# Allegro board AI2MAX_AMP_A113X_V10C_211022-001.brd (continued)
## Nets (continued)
GND: C1.2 C2.2 C3.2 C4.2 C6.2 C7.2 C9.1 C12.1 C13.2 C14.1 C16.2 C17.1 C18.2 C20.1 C21.2 C22.2 C25.1 C30.2 C51.2 C52.1 C54.2 C55.1 C56.2 C57.2 C58.1 C60.2 C61.1 C62.2 C65.1 C66.1 C67.1 C68.2 C69.1 C71.2 C72.1 C73.2 C75.1 C76.2 C77.2 C78.2 C79.2 C101.1 C102.1 C103.1 C104.1 C105.1 C106.1 C201.2 C203.1 C204.1 C205.2 C206.2 C207.1 C208.1 C209.2 C211.2 C214.2 C216.1 C217.1 C218.2 C219.1 C221.1 C222.1 C223.2 C224.2 C226.1 C228.1 C229.1 C230.2 C231.2 C232.1 C233.2 C235.2 C238.2 C240.1 C241.1 C242.2 C243.1 C245.1 C246.1 C248.2 C249.2 C250.1 C251.1 C252.1 C253.1 C254.1 C255.2 C256.2 C257.2 C258.2 C259.1 C260.2 C261.1 C262.2 C264.2 C265.1 C268.2 C269.1 C301.2 C303.1 C304.1 C305.2 C306.2 C307.1 C308.1 C309.2 C311.2 C314.2 C316.1 C317.1 C318.2 C319.1 C321.1 C322.1 C323.2 C324.2 C326.1 C328.1 C329.1 C330.2 C331.2 C332.1 C333.2 C335.2 C338.2 C340.1 C341.1 C342.2 C343.1 C345.1 C346.1 C348.2 C349.1 C350.1 C351.1 C352.1 C353.2 C354.2 C355.2 C356.2 C357.1 C358.2 C359.1 C360.2 C362.2 C363.1 C366.2 C367.1 J813.3 J813.9 J813.13 J813.15 J813.S1 J813.S2 J813.S3 J813.S4 J813.S5 J814.5(GND#5) J814.6(S1) J814.7(S2) J814.8(S3) J814.9(S4) J814.10(GND#10) J814.11(GND#11) Q2.2(EMITTER) Q3.2(EMITTER) Q4.2(EMITTER) Q5.2(EMITTER) R3.1 R7.1 R9.1 R11.1 R21.1 R22.1 R59.1 R60.1 R63.1 R201.2 R204.1 R205.2 R207.1 R220.1 R221.2 R223.1 R233.1 R234.2 R235.1 R236.2 R301.2 R304.1 R305.2 R319.1 R321.2 R339.1 R340.2 R341.1 R342.2 T1.2 T308.1(TP) T311.1(TP) T312.1(TP) T313.1(TP) T314.1(TP) T315.1(TP) T318.1(TP) T320.1(TP) T321.1(TP) U1.A9(DVSS#A9) U1.A14(DVSS#A14) U1.B4(DVSS#B4) U1.B17(DVSS#B17) U1.D5(DVSS#D5) U1.D7(DVSS#D7) U1.D9(DVSS#D9) U1.D12(DVSS#D12) U1.D14(DVSS#D14) U1.E4(DVSS#E4) U1.E5(DVSS#E5) U1.E6(DVSS#E6) U1.E7(DVSS#E7) U1.E8(DVSS#E8) U1.E9(DVSS#E9) U1.E10(DVSS#E10) U1.E11(DVSS#E11) U1.E12(DVSS#E12) U1.E13(DVSS#E13) U1.F3(DVSS#F3) U1.F4(DVSS#F4) U1.F7(DVSS#F7) U1.F8(DVSS#F8) U1.F9(DVSS#F9) U1.F10(DVSS#F10) U1.F11(DVSS#F11) U1.F14(DVSS#F14) U1.G7(DVSS#G7) U1.G8(DVSS#G8) U1.G9(DVSS#G9) U1.G10(DVSS#G10) U1.G11(DVSS#G11) U1.G12(DVSS#G12) U1.G13(DVSS#G13) U1.H1(DVSS#H1) U1.H6(DVSS#H6) U1.H7(DVSS#H7) U1.H8(DVSS#H8) U1.H9(DVSS#H9) U1.H10(DVSS#H10) U1.H11(DVSS#H11) U1.H14(DVSS#H14) U1.H15(DVSS#H15) U1.J7(DVSS#J7) U1.J8(DVSS#J8) U1.J9(DVSS#J9) U1.J10(DVSS#J10) U1.J11(DVSS#J11) U1.J14(DVSS#J14) U1.J17(DVSS#J17) U1.K2(DVSS#K2) U1.K4(DVSS#K4) U1.K5(DVSS#K5) U1.K6(DVSS#K6) U1.K7(DVSS#K7) U1.K8(DVSS#K8) U1.K9(DVSS#K9) U1.K10(DVSS#K10) U1.K12(DVSS#K12) U1.K13(DVSS#K13) U1.L4(DVSS#L4) U1.L5(DVSS#L5) U1.L6(DVSS#L6) U1.L7(DVSS#L7) U1.L8(DVSS#L8) U1.L9(DVSS#L9) U1.L11(DVSS#L11) U1.L12(DVSS#L12) U1.L13(DVSS#L13) U1.L14(DVSS#L14) U1.L15(DVSS#L15) U1.M4(DVSS#M4) U1.M5(DVSS#M5) U1.M9(DVSS#M9) U1.M12(DVSS#M12) U1.M13(DVSS#M13) U1.M14(DVSS#M14) U1.M17(DVSS#M17) U1.N2(DVSS#N2) U1.N3(DVSS#N3) U1.N6(DVSS#N6) U1.N7(DVSS#N7) U1.N9(DVSS#N9) U1.N10(DVSS#N10) U1.N15(DVSS#N15) U1.P2(DVSS#P2) U1.P3(DVSS#P3) U1.P4(DVSS#P4) U1.P5(DVSS#P5) U1.P8(DVSS#P8) U1.P11(DVSS#P11) U1.P14(DVSS#P14) U1.R3(DVSS#R3) U1.R8(DVSS#R8) U1.R17(DVSS#R17) U1.T1(DVSS#T1) U1.T5(DVSS#T5) U1.T9(DVSS#T9) U1.T12(DVSS#T12) U1.T15(DVSS#T15) U1.U3(DVSS#U3) U1.U6(DVSS#U6) U1.U10(DVSS#U10) U1.U13(DVSS#U13) U1.U16(DVSS#U16) U2.4(GND) U2.9(E-PAD) U3.2(GND) U51.2(GND) U52.2(GND) U53.2(GND) U54.2(GND) U55.2(GND) U201.1(NC1) U201.3(NC2) U201.4(GND) U201.5(NC3) U201.9(NC4) U201.17(PGND2B) U201.22(PGND2A) U201.25(AGND) U201.26(NC5) U201.29(PGND1B) U201.34(PGND1A) U201.39(GND_IO) U201.41(E_PAD) U202.1(NC1) U202.3(NC2) U202.4(GND) U202.5(NC3) U202.9(NC4) U202.17(PGND2B) U202.22(PGND2A) U202.25(AGND) U202.26(NC5) U202.29(PGND1B) U202.34(PGND1A) U202.39(GND_IO) U202.41(E_PAD) U301.1(NC1) U301.3(NC2) U301.4(GND) U301.5(NC3) U301.9(NC4) U301.17(PGND2B) U301.22(PGND2A) U301.25(AGND) U301.26(NC5) U301.29(PGND1B) U301.34(PGND1A) U301.39(GND_IO) U301.41(E_PAD) U302.1(NC1) U302.3(NC2) U302.4(GND) U302.5(NC3) U302.9(NC4) U302.17(PGND2B) U302.22(PGND2A) U302.25(AGND) U302.26(NC5) U302.29(PGND1B) U302.34(PGND1A) U302.39(GND_IO) U302.41(E_PAD) UNK2C1.1 UNK2C2.1 UNK2C3.1 UNK2C4.2 UNK2C5.1 UNK2C6.2 UNK2C7.1 UNK2C8.1 UNK2C9.1 UNK2C10.1 UNK2C11.1 UNK2C12.1 UNK2C13.2 UNK2C14.1 UNK2C15.1 UNK2C16.1 UNK2C17.2 UNK2C19.1 UNK2C20.1 UNK2C22.1 UNK2CON1.1 UNK2D3.2 UNK2D4.2 UNK2Q1.2 UNK2R14.2 UNK2R15.1 UNK2T17.1 UNK2T25.1 UNK2T28.1 UNK2U2.1 UNK2Y2.2 UNK2Y2.4 UNK3C1.1 UNK3C2.1 UNK3C4.1 UNK3C5.1 UNK3C6.2 UNK3C8.2 UNK3C9.1 UNK3C10.1 UNK3C11.1 UNK3C12.1 UNK3C18.1 UNK3C19.1 UNK3C20.1 UNK3C21.1 UNK3C26.2 UNK3C27.1 UNK3C28.2 UNK3C30.1 UNK3C31.1 UNK3C35.1 UNK3C38.1 UNK3C39.1 UNK3C40.1 UNK3C42.1 UNK3C45.1 UNK3C46.1 UNK3C58.1 UNK3C62.1 UNK3R6.1 UNK3R10.1 UNK3R20.1 UNK3U1.A9 UNK3U1.B1 UNK3U1.B3 UNK3U1.B9 UNK3U1.D1 UNK3U1.D8 UNK3U1.E1 UNK3U1.E2 UNK3U1.E8 UNK3U1.F9 UNK3U1.G1 UNK3U1.G8 UNK3U1.G9 UNK3U1.J2 UNK3U1.J8 UNK3U1.M1 UNK3U1.M9 UNK3U1.P1 UNK3U1.P9 UNK3U1.T1 UNK3U1.T9 UNK4C2.1 UNK4C3.1 UNK4C4.1 UNK4C5.2 UNK4C8.1 UNK4C9.1 UNK4C10.1 UNK4C11.1 UNK4C17.1 UNK4C18.1 UNK4C26.1 UNK4C34.1 UNK4C35.1 UNK4C47.2 UNK4C48.1 UNK4C49.1 UNK4K2.1 UNK4K2.2 UNK4R2.1 UNK4R7.1 UNK4R9.2 UNK4R13.1 UNK4R52.1 UNK4U5.2 UNK4U5.13 UNK4U5.23 UNK4U5.25 UNK4U5.27 UNK4U5.33 UNK4U5.36 UNK4U5.40 UNK4U5.46 UNK4U5.48 UNK4U9.AA4 UNK4U9.AA6 UNK4U9.H6 UNK4U9.K4 UNK4U9.M7 UNK4U9.P5 UNK4U9.R10 UNK4U9.T5 UNK4U9.U8 UNK4U9.Y2 UNK4U9.Y5 UNK5C3.1 UNK5C9.1 UNK5C10.1 UNK5C11.1 UNK5C13.1 UNK5D11.2 UNK5D12.2 UNK5R64.2 UNK5R78.2
VCC5V: C6.1 C7.1 C9.2 C10.2 C13.1 C14.2 C51.1 C52.2 C57.1 C58.2 C68.1 C69.2 J814.1(VBUS) L1.2 R6.2 R10.2 R17.1 R18.1 R52.2 R329.1 R330.1 R334.1 R337.2 U3.5(IN) U51.5(IN) U52.5(IN) U53.5(IN) UNK5C13.2 UNK5R5.1
VCC_3.3V: C22.1 C79.1 Q1.3(D) U1.A5(VDDIO_Z) U1.K15(AVDD33_USB) U55.1(VIN) U55.3(ON/OFF) UNK2C22.2 UNK2R18.1 UNK2R19.1 UNK2T15.1 UNK4C4.2 UNK4C5.1 UNK4C8.2 UNK4C17.2 UNK4C18.2 UNK4C49.2 UNK4R6.2 UNK4U5.1 UNK4U5.12 UNK4U5.24 UNK4U5.37 UNK4U9.M6 UNK4U9.N5 UNK4U9.T10 UNK4U9.U9 UNK5C10.2
VDD_EE: C60.1 C61.2 C62.1 C64.2 L52.2 R15.2 R53.2 R333.2 U1.F12(VDD_EE#F12) U1.J3(VDD_EE#J3) U1.J4(VDD_EE#J4) U1.J5(VDD_EE#J5) U1.J6(VDD_EE#J6) U1.K11(VDD_EE#K11) UNK1R2.2 UNK2C1.2 UNK2C11.2 UNK2C13.1 UNK2C16.2 UNK2C20.2 UNK2R27.2
VDDAO_3.3V: C16.1 C17.2 C18.1 C19.2 C21.1 C23.2 C101.2 C201.1 C230.1 C249.1 C250.2 C301.1 C330.1 L2.2 Q1.2(S) R8.2 R12.2 R62.1 R105.1 R214.2 R307.1 R314.2 R323.1 R335.1 R336.1 R348.1 R349.1 R350.1 R351.1 T129.1(TP) T316.1(TP) T319.1(TP) U1.D13(VDDIO_AO) U1.K14(VDDIO_A) U201.40(VDD_IO) U202.40(VDD_IO) U301.40(VDD_IO) U302.40(VDD_IO) UNK2C5.2 UNK2C15.2 UNK2CON1.3 UNK2D7.1 UNK2R2.1 UNK2R24.1 UNK2R28.1 UNK2U2.3
VDDCPU: C54.1 C55.2 C56.1 C63.2 L51.2 R51.2 U1.F5(VDDCPU#F5) U1.F6(VDDCPU#F6) U1.G3(VDDCPU#G3) U1.G4(VDDCPU#G4) U1.G5(VDDCPU#G5) U1.G6(VDDCPU#G6) U1.H3(VDDCPU#H3) U1.H4(VDDCPU#H4) U1.H5(VDDCPU#H5) UNK1R1.2 UNK2C2.2 UNK2C4.1 UNK2C6.1 UNK2C7.2 UNK2C8.2 UNK2C14.2 UNK2C19.2
VDDCPU_EN: R54.1 U1.C4(TESTN) UNK2R2.2
VDDCPU_PWM: R56.2 U1.D3(GPIOAO_2//UART_CTS_AO_B//UART_C) UNK1R1.1
VDDEE_PWM: R58.2 U1.D4(GPIOAO_9//I2C_SDA_AO//PWMAO_D) UNK1R2.1
VDDIO_AO18: C76.1 R106.1 U1.H12(AVDD18_SAR_PLL) U1.H13(VDD18_XTAL_IOVREF) U1.J12(AVDD18_DDRPLL) U1.J13(AVDD18_USB) U54.5(VOUT) UNK2C10.2 UNK2C12.2 UNK2C17.1 UNK2R3.2 UNK2R29.2 UNK3C1.2 UNK5C9.2 UNK5R20.1
VDDIO_BOOT: U1.L3(VDDIO_BOOT) UNK4C2.2 UNK4C10.2 UNK4C11.2 UNK4C34.2 UNK4C35.2 UNK4C47.1 UNK4C48.2 UNK4R1.2 UNK4R3.1 UNK4R4.1 UNK4R5.1 UNK4R6.1 UNK4R8.1 UNK4R12.2 UNK4R14.1 UNK4R16.1 UNK4U5.28 UNK4U5.34 UNK4U5.45 UNK4U9.AA3 UNK4U9.AA5 UNK4U9.K6 UNK4U9.W4 UNK4U9.Y4
VDDIO_X: C102.2 R105.2 R106.2 U1.C8(VDDIO_X)
VDDQ1.35V: C71.1 C72.2 C73.1 C74.2 L53.2 R61.2 U1.M6(VDDQ#M6) U1.M7(VDDQ#M7) U1.M8(VDDQ#M8) U1.M10(VDDQ#M10) U1.M11(VDDQ#M11) U1.N4(VDDQ#N4) U1.N5(VDDQ#N5) UNK3C2.2 UNK3C4.2 UNK3C5.2 UNK3C6.1 UNK3C8.1 UNK3C9.2 UNK3C10.2 UNK3C11.2 UNK3C12.2 UNK3C18.2 UNK3C19.2 UNK3C20.2 UNK3C21.2 UNK3C26.1 UNK3C28.1 UNK3C30.2 UNK3C31.2 UNK3C35.2 UNK3C38.2 UNK3C39.2 UNK3C42.2 UNK3C45.2 UNK3C58.2 UNK3C62.2 UNK3R8.2 UNK3R19.2 UNK3U1.A1 UNK3U1.A8 UNK3U1.B2 UNK3U1.C1 UNK3U1.C9 UNK3U1.D2 UNK3U1.D9 UNK3U1.E9 UNK3U1.F1 UNK3U1.G7 UNK3U1.H2 UNK3U1.H9 UNK3U1.K2 UNK3U1.K8 UNK3U1.N1 UNK3U1.N9 UNK3U1.R1 UNK3U1.R9
ACTIVE_STBY: R219.1 R320.1 U1.B11(GPIOX_19//I2C_SDA_C//UART_CTS_E)
AMP_RESET: R215.1 R315.1 T317.1(TP) UNK5R74.2
AMP_SCL: R209.1 U1.A16(GPIOAO_10//I2C_SLAVE_SCK_AO//I2) UNK2R24.2 UNK5R66.2
AMP_SCL_DEV: R209.2 R238.1 R309.1 T306.1(TP)
AMP_SDA: R210.1 U1.B15(GPIOAO_11//I2C_SLAVE_SDA_AO//I2) UNK2R28.2 UNK5R65.2
AMP_SDA_DEV: R210.2 R239.1 R310.1 T305.1(TP)
BCLK: J813.11 UNK5R68.1
CPU_RESET: R240.1 R338.1 U1.A12(RESETN) UNK2R14.1 UNK2U2.2
CTRL_A113X: UNK5R75.2 UNK5R76.1 UNK5R77.1
DATA: J813.12 UNK5R69.1
DDR3_A0: U1.R12(A0) UNK3U1.N3
DDR3_A1: U1.U15(A1) UNK3U1.P7
DDR3_A2: U1.P16(A2) UNK3U1.P3
DDR3_A3: U1.U17(A3) UNK3U1.N2
DDR3_A4: U1.R11(A4) UNK3U1.P8
DDR3_A5: U1.T14(A5) UNK3U1.P2
DDR3_A6: U1.P12(A6) UNK3U1.R8
DDR3_A7: U1.U14(A7) UNK3U1.R2
DDR3_A8: U1.P13(A8) UNK3U1.T8
DDR3_A9: U1.T16(A9) UNK3U1.R3
DDR3_A10: U1.R10(A10) UNK3U1.L7
DDR3_A11: U1.P17(A11) UNK3U1.R7
DDR3_A12: U1.T17(A12) UNK3U1.N7
DDR3_A13: U1.R15(A13) UNK3U1.T3
DDR3_A14: U1.R14(A14(A14/WE_N)) UNK3U1.T7
DDR3_A15: U1.T13(A15(A15/CAS_N)) UNK3U1.M7
DDR3_BA0: U1.N16(BA_0) UNK3U1.M2
DDR3_BA1: U1.U12(BA_1) UNK3U1.N8
DDR3_BA2: U1.M16(BA_2(BG0)) UNK3U1.M3
DDR3_CAS: U1.P15(CAS_N(ACT_N)) UNK3U1.K3
DDR3_CKE0: U1.P10(CKE0) UNK3U1.K9
DDR3_CLKN: U1.T10(CKN) UNK3C7.1 UNK3R2.2 UNK3U1.K7
DDR3_CLKP: U1.U9(CKP) UNK3C7.2 UNK3R2.1 UNK3U1.J7
DDR3_DQ0: U1.T2(DQ0) UNK3U1.A2
DDR3_DQ1: U1.T3(DQ1) UNK3U1.C2
DDR3_DQ2: U1.P6(DQ2) UNK3U1.A7
DDR3_DQ3: U1.U7(DQ3) UNK3U1.D7
DDR3_DQ4: U1.U1(DQ4) UNK3U1.A3
DDR3_DQ5: U1.U2(DQ5) UNK3U1.C3
DDR3_DQ6: U1.R6(DQ6) UNK3U1.B8
DDR3_DQ7: U1.T7(DQ7) UNK3U1.C8
DDR3_DQ8: U1.T8(DQ8) UNK3U1.H7
DDR3_DQ9: U1.R2(DQ9) UNK3U1.F2
DDR3_DQ10: U1.R9(DQ10) UNK3U1.H8
DDR3_DQ11: U1.R4(DQ11) UNK3U1.E3
DDR3_DQ12: U1.R7(DQ12) UNK3U1.F8
DDR3_DQ13: U1.P1(DQ13) UNK3U1.H3
DDR3_DQ14: U1.P9(DQ14) UNK3U1.F7
DDR3_DQ15: U1.R1(DQ15) UNK3U1.G2
DDR3_DQM0: U1.R5(DQM0) UNK3U1.D3
DDR3_DQM1: U1.P7(DQM1) UNK3U1.E7
DDR3_DQSN0: U1.T6(DQSN_0) UNK3U1.B7
DDR3_DQSN1: U1.T4(DQSN_1) UNK3U1.G3
DDR3_DQSP0: U1.U5(DQSP_0) UNK3U1.C7
DDR3_DQSP1: U1.U4(DQSP_1) UNK3U1.F3
DDR3_NCS0: U1.U11(CS0_N) UNK3U1.L2
DDR3_ODT0: U1.R16(ODT0) UNK3U1.K1
DDR3_RAS: U1.T11(RAS_N(A16/RAS_N)) UNK3U1.J3
DDR3_RST: U1.M15(RST_N) UNK3C46.2 UNK3R8.1 UNK3U1.T2
DDR3_WE: U1.R13(WE_N(BG1)) UNK3U1.L3
EMMC_1.8V: C77.1 U55.5(VOUT) UNK4R5.2
GPIOX_16: T125.1(TP) U1.D10(GPIOX_16//I2C_SCK_B//UART_TX_EE)
GPIOX_17: T126.1(TP) U1.D8(GPIOX_17//I2C_SDA_B//UART_RX_EE)
GPIOX_18: T127.1(TP) U1.C10(GPIOX_18//I2C_SCK_C//UART_RTS_E)
GPIOZ_10: U1.E2(GPIOZ_10) UNK2T3.1
HW_VS: U1.D15(SARADC_CH1) UNK2R3.1 UNK2R15.2
I2SIN_BCLK_C: C103.2 R107.2 R227.1 R229.1 R325.1 R327.1 R343.2 T309.1(TP) UNK5R68.2
I2SIN_DATA_C: R103.2 R104.2 UNK5R69.2
I2SIN_LRCK_C: C104.2 R108.2 R228.1 R230.1 R326.1 R328.1 R344.2 T307.1(TP) UNK5R67.2
I2SIN_MCLK_B: R102.2 UNK5R70.2
I2SO_DATA0: C105.2 R109.2 R225.2 R231.2 U201.7(SDATA) U301.7(SDATA)
I2SO_DATA1: C106.2 R110.2 R226.2 R231.1 U202.7(SDATA) U302.7(SDATA)
I2SO_MCLK_A: R101.2 T101.1(TP)
IR_IN: U1.B14(GPIOAO_6//IR_REMOTE_INPUT) UNK2T6.1
IR_OUT: U1.B13(GPIOAO_7//IR_REMOTE_OUT//JTAG_T) UNK2T5.1
LCD_BL_EN: U1.B1(GPIOZ_5//SPI_SS2_A//PWM_A//SPDI) UNK2T21.1
LCD_BL_PWM: U1.C7(GPIOZ_4//SPI_SS1_A//PWM_B//SPDI) UNK2T22.1
LCD_RESET: U1.C2(GPIOZ_6//I2C_SCK_A//UART_CTS_AO) UNK2T24.1
LINE_OUT_DET: U1.D2(GPIOZ_7//I2C_SDA_A//UART_RTS_AO) UNK2T23.1
LINUX_RX: U1.B12(GPIOAO_1//UART_RX_AO_A) UNK2D4.1 UNK2R1.2
LINUX_TX: U1.A13(GPIOAO_0//UART_TX_AO_A) UNK2D3.1 UNK2R16.2
LRCK: J813.10 UNK5R67.1
MCLK: J813.14 UNK5R70.1
MDDR3_VREF1: UNK3C27.2 UNK3C40.2 UNK3R19.1 UNK3R20.2 UNK3U1.H1 UNK3U1.M8
NAND_ALE: U1.M1(BOOT_9//EMMC_RST//NAND_ALE//NOR) UNK4U5.17 UNK4U9.U5
NAND_CLE: U1.L2(BOOT_10//EMMC_CMD//NAND_CLE) UNK4R14.2 UNK4U5.16 UNK4U9.W5
NAND_CS1: U1.L1(BOOT_8//EMMC_CLK//NAND_CE0) UNK4C3.2 UNK4R1.1 UNK4R11.1 UNK4R11.2 UNK4U5.9 UNK4U9.W6
NAND_D0: U1.F2(BOOT_0//EMMC_D0) UNK4R16.2 UNK4R19.1 UNK4R19.2 UNK4U5.29 UNK4U9.H3
NAND_D1: U1.F1(BOOT_1//EMMC_D1) UNK4R20.1 UNK4R20.2 UNK4U5.30 UNK4U9.H4
NAND_D2: U1.G1(BOOT_2//EMMC_D2) UNK4R21.1 UNK4R21.2 UNK4U5.31 UNK4U9.H5
NAND_D3: U1.G2(BOOT_3//EMMC_D3//NOR_HOLDN) UNK4R22.1 UNK4R22.2 UNK4U5.32 UNK4U9.J2
NAND_D4: U1.H2(BOOT_4//EMMC_D4//NOR_D//POC0) UNK4R23.1 UNK4R23.2 UNK4R52.2 UNK4U5.41 UNK4U9.J3
NAND_D5: U1.J1(BOOT_5//EMMC_D5//NOR_Q//POC1) UNK4R10.2 UNK4R24.1 UNK4R24.2 UNK4U5.42 UNK4U9.J4
NAND_D6: U1.J2(BOOT_6//EMMC_D6//NOR_C//POC2) UNK4R13.2 UNK4R25.1 UNK4R25.2 UNK4U5.43 UNK4U9.J5
NAND_D7: U1.K1(BOOT_7//EMMC_D7//POC3) UNK4R2.2 UNK4R26.1 UNK4R26.2 UNK4U5.44 UNK4U9.J6
NAND_NR/B: U1.K3(BOOT_13//EMMC_DS//NAND_RB) UNK4R9.1 UNK4R12.1 UNK4R17.1 UNK4U5.6 UNK4U5.7
NAND_NRE: U1.M2(BOOT_12//NAND_REN_WR) UNK4R18.1 UNK4R18.2 UNK4U5.8
NAND_NWE: U1.N1(BOOT_11//NAND_WEN_CLK) UNK4R15.1 UNK4R15.2 UNK4U5.18
NAND_PSL: UNK4R3.2 UNK4U5.39
NAND_VSP: UNK4R7.2 UNK4R8.2 UNK4U5.38
NPWM_OFF1: R219.2 U201.12(\\F\A\U\L\T) U202.12(\\F\A\U\L\T)
NPWM_OFF2: R320.2 U301.12(\\F\A\U\L\T) U302.12(\\F\A\U\L\T)
NRESET_AMP: R216.1 R316.1 U1.B6(GPIOX_20//PWM_A)
NRST_AMP1: C204.2 C226.2 R215.2 R216.2 R240.2 U201.36(\\R\E\S\E\T) U202.36(\\R\E\S\E\T)
NRST_AMP2: C304.2 C326.2 R315.2 R316.2 R338.2 U301.36(\\R\E\S\E\T) U302.36(\\R\E\S\E\T)
OUT1A_B_LF: C233.1 C237.1 C261.2 C267.1 FB203.1 L203.2 L213.2 R220.2
OUT1A_B_LW: C209.1 C213.1 C259.2 C263.1 FB202.2 L201.2 L211.2 R204.2
OUT1A_B_RF: C333.1 C337.1 C359.2 C365.1 FB303.1 L303.2 L313.2 R319.2
OUT1A_B_RW: C309.1 C313.1 C357.2 C361.1 FB302.2 L301.2 L311.2 R304.2
OUT2A_B_LF: C237.2 C240.2 C262.1 C270.2 FB204.1 L204.2 L214.2 R221.1
OUT2A_B_LW: C213.2 C216.2 C260.1 C266.2 FB201.2 L202.2 L212.2 R205.1
OUT2A_B_RF: C337.2 C340.2 C360.1 C368.2 FB304.1 L304.2 L314.2 R321.1
OUT2A_B_RW: C313.2 C316.2 C358.1 C364.2 FB301.2 L302.2 L312.2 R305.1
PDM_DCLK: T102.1(TP) U1.E16(GPIOA_14//PDM_DCLK//CLKSYN_IN//)
PDM_DIN0: T103.1(TP) U1.E17(GPIOA_15//PDM_DIN0//PWM_B)
PDM_DIN1: T104.1(TP) U1.D16(GPIOA_16//PDM_DIN1//PWM_C)
PDM_DIN2: T105.1(TP) U1.D17(GPIOA_17//PDM_DIN2//I2C_SDA_C//)
PDM_DIN3: T106.1(TP) U1.C17(GPIOA_18//PDM_DIN3//I2C_SCK_C//)
POWERSTB: R12.1 R13.1 U1.C12(GPIOAO_12//CLK12_24//PWMAO_B)
PVREF: U1.N11(PVREF) UNK3T1.1
PWR_24V: C1.1 C2.1 C3.1 C4.1 C30.1 C205.1 C206.1 C223.1 C224.1 C231.1 C248.1 C255.1 C256.1 C257.1 C258.1 C305.1 C306.1 C323.1 C324.1 C331.1 C348.1 C353.1 C354.1 C355.1 C356.1 R1.2 T1.1 U2.2(VIN) U201.19(PVDD2B) U201.20(PVDD2A) U201.31(PVDD1B) U201.32(PVDD1A) U202.19(PVDD2B) U202.20(PVDD2A) U202.31(PVDD1B) U202.32(PVDD1A) U301.19(PVDD2B) U301.20(PVDD2A) U301.31(PVDD1B) U301.32(PVDD1A) U302.19(PVDD2B) U302.20(PVDD2A) U302.31(PVDD1B) U302.32(PVDD1A)
RMII_MDC: T322.1(TP) U1.A11(GPIOX_22//ETH_MDC)
RMII_MDIO: T323.1(TP) U1.A8(GPIOX_21//ETH_MDIO)
RMII_RXCLK: T325.1(TP) U1.B7(GPIOX_12//TDMA_SCLK//TDMA_SLV_S)
RMII_RXD0: T327.1(TP) U1.B8(GPIOX_13//TDMA_FS//TDMA_SLV_FS/)
RMII_RXD1: T326.1(TP) U1.A6(GPIOX_14//TDMA_DIN0//TDMA_DOUT0)
RMII_RXDV: T324.1(TP) U1.A7(GPIOX_15//TDMA_DOUT0//TDMA_DOUT)
RMII_TXD0: T328.1(TP) U1.A10(GPIOX_8//UART_TX_EE_A//RMII_TXD)
RMII_TXD1: T331.1(TP) U1.C9(GPIOX_9//UART_RX_EE_A//RMII_TXD)
RMII_TXEN: T329.1(TP) U1.B9(GPIOX_10//UART_CTS_EE_A//PWM_C/)
SCL: J813.8 UNK5R66.1
SCL_AMP1: C222.2 C246.2 R211.2 R238.2 R349.2 U201.11(SCL) U202.11(SCL)
SCL_AMP2: C322.2 C346.2 R309.2 R311.2 R351.2 U301.11(SCL) U302.11(SCL)
SDA: J813.7 UNK5R65.1
SDA_AMP1: C217.2 C241.2 R212.2 R239.2 R348.2 U201.10(SDA) U202.10(SDA)
SDA_AMP2: C317.2 C341.2 R310.2 R312.2 R350.2 U301.10(SDA) U302.10(SDA)
SPDIF_IN: T107.1(TP) U1.E14(GPIOA_19//SPDIF_IN//SPDIF_OUT//)
SPDIF_OUT: T108.1(TP) U1.C16(GPIOA_20//SPDIF_OUT//SPDIF_IN//)
SPI_CLK: U1.C6(GPIOZ_0//SPI_CLK_A//UART_RTS_EE) UNK2T16.1
SPI_MISO: U1.D6(GPIOZ_2//SPI_MISO_A//UART_TX_EE) UNK2T19.1
SPI_MOSI: U1.C5(GPIOZ_1//SPI_MOSI_A//UART_CTS_E) UNK2T18.1
SPI_SS0: U1.C1(GPIOZ_3//SPI_SS0_A//UART_RX_EE_) UNK2T20.1
SPK_I2C_SCK: R211.1 R311.1 U1.E3(GPIOZ_8//I2C_SCK_B//UART_TX_AO_) UNK2R18.2 UNK2T26.1
SPK_I2C_SDA: R212.1 R312.1 U1.D1(GPIOZ_9//I2C_SDA_B//UART_RX_AO_) UNK2R19.2 UNK2T27.1
SPK_RST: U1.C15(GPIOAO_4//UART_TX_AO_B//I2C_SCK) UNK2T8.1
STANDBY_A113X: U1.C13(GPIOAO_8//CLK_32K_IN//I2C_SCK_A) UNK5R77.2
SYS_LED: U1.A15(GPIOAO_3//UART_RTS_AO_B//UART_R) UNK2R8.2
USB_PWR_EN: U1.C11(GPIOAO_5//UART_RX_AO_B//I2C_SDA) UNK2T7.1
USB_TXRTUNE: U1.J15(USB_TXRTUNE) UNK5R64.1
USBOTG_A_DM: U1.L16(USB_DM) UNK5D12.1 UNK5R71.2 UNK5R84.2
USBOTG_A_DP: U1.L17(USB_DP) UNK5D11.1 UNK5R72.2 UNK5R85.2
USBOTG_A_ID: U1.K17(USB_ID) UNK5C3.2 UNK5R20.2 UNK5R76.2 UNK5R78.1 UNK5R83.2
USBOTG_A_VBUS: U1.K16(USB_VBUS) UNK5C11.2 UNK5R5.2
WPN: UNK4C9.2 UNK4R4.2 UNK4U5.19
N21450221: C23.1 Q1.1(G) R13.2
N21455517: U1.F13(VDDAO_0V9) UNK2R27.1
N21455804: U1.E15(SARADC_CH0) UNK2R29.1
N21455846: UNK2Q1.3 UNK2R12.2
N21455854: UNK2D7.2 UNK2R12.1
N21456017: U1.D11(GPIOAO_13//CLK25_EE//GEN_CLK_AO) UNK2T29.1
N21456060: U1.B16(SYS_OSCIN) UNK2C3.2 UNK2R5.1 UNK2Y2.1
N21456068: U1.A17(SYS_OSCOUT) UNK2R10.2
N21456125: UNK2C9.2 UNK2R5.2 UNK2R10.1 UNK2Y2.3
N21456352: UNK2CON1.4 UNK2R1.1
N21456391: UNK2CON1.2 UNK2R16.1
N21464427: U1.N8(PZQ) UNK3R6.2
N21467829: U1.M3(BOOT_14//NOR_CS) UNK4T25.1
N21468142: UNK4K2.3 UNK4K2.4 UNK4R10.1
N21476089: R101.1 U1.J16(GPIOA_0//MCLK_C//CLKSYN_IN//PWM)
N21476146: R102.1 U1.H17(GPIOA_1//MCLK_B//SPDIF_IN//SPDI)
N21492258: C53.2 L51.1 U51.6(LX)
N21492341: C65.2 R54.2 R337.1 U51.4(EN)
N21492347: C53.1 U51.1(BS)
N21492451: C63.1 R51.1 R55.1 R59.2 U51.3(FB)
N21492734: C66.2 R55.2 R56.1
N21494202: C78.1 R334.2 R335.2 U54.1(VIN)
N21494218: R331.1 R336.2 U54.3(ON/OFF)
N21499562: C59.2 L52.1 U52.6(LX)
N21499612: R52.1 U52.4(EN)
N21499616: C59.1 U52.1(BS)
N21499652: C64.1 R53.1 R57.1 R60.2 U52.3(FB)
N21499757: C67.2 R57.2 R58.1
N21500929: C70.2 L53.1 U53.6(LX)
N21500979: C75.2 R62.2 U53.4(EN)
N21500983: C70.1 U53.1(BS)
N21501019: C74.1 R61.1 R63.2 U53.3(FB)
N21506095: C15.2 L2.1 U3.6(LX)
N21506141: C20.2 R6.1 R7.2 R19.1 U3.4(EN)
N21506145: C15.1 U3.1(BS)
N21506181: C19.1 R8.1 R9.2 U3.3(FB)
N21534101: UNK3R10.2 UNK3U1.L8
N21597998: UNK2Q1.1 UNK2R8.1
N21714583: C202.2 C210.1 L201.1 L211.1 R202.2 R203.1 U201.30(OUT1B) U201.33(OUT1A)
N21714609: C251.2 R227.2 U201.38(BCK)
N21714673: C203.2 R202.1
N21714680: C202.1 U201.35(BST1A)
N21714717: R201.1 U201.37(AD)
N21714779: C207.2 R203.2
N21714803: C208.2 U201.2(VDD_PLL)
N21714950: C210.2 U201.28(BST1B)
N21714966: C211.1 U201.27(VDR1)
N21715014: C218.1 U201.6(DVDD)
N21715038: C214.1 U201.24(VDR2)
N21715056: C215.2 U201.23(BST2A)
N21715058: C215.1 C220.1 L202.1 L212.1 R206.2 R208.1 U201.18(OUT2B) U201.21(OUT2A)
N21715192: C219.2 R206.1
N21715198: T201.1(TP) U201.13(MONITOR_0)
N21715200: R207.2 U201.14(MONITOR_1)
N21715202: T202.1(TP) U201.15(MONITOR_2)
N21715204: C220.2 U201.16(BST2B)
N21715315: C221.2 R208.2
N21715401: FB202.1 J803.1
N21715403: FB201.1 J803.2
N21715405: FB203.2 J803.4
N21715413: FB204.2 J803.3
N21715441: C225.2 C234.1 L203.1 L213.1 R213.2 R217.1 U202.30(OUT1B) U202.33(OUT1A)
N21715461: C253.2 R229.2 U202.38(BCK)
N21715523: C228.2 R213.1
N21715527: C225.1 U202.35(BST1A)
N21715561: R214.1 U202.37(AD)
N21715623: C229.2 R217.2
N21715647: C232.2 U202.2(VDD_PLL)
N21715792: C234.2 U202.28(BST1B)
N21715808: C235.1 U202.27(VDR1)
N21715856: C242.1 U202.6(DVDD)
N21715880: C238.1 U202.24(VDR2)
N21715898: C239.2 U202.23(BST2A)
N21715900: C239.1 C244.1 L204.1 L214.1 R222.2 R224.1 U202.18(OUT2B) U202.21(OUT2A)
N21716032: C243.2 R222.1
N21716038: T203.1(TP) U202.13(MONITOR_0)
N21716040: R223.2 U202.14(MONITOR_1)
N21716042: T204.1(TP) U202.15(MONITOR_2)
N21716044: C244.2 U202.16(BST2B)
N21716155: C245.2 R224.2
N21722582: C302.2 C310.1 L301.1 L311.1 R302.2 R303.1 U301.30(OUT1B) U301.33(OUT1A)
N21722605: C349.2 R325.2 U301.38(BCK)
N21722669: C303.2 R302.1
N21722673: C302.1 U301.35(BST1A)
N21722707: R301.1 U301.37(AD)
N21722769: C307.2 R303.2
N21722793: C308.2 U301.2(VDD_PLL)
N21722936: C310.2 U301.28(BST1B)
N21722954: C311.1 U301.27(VDR1)
N21722998: C318.1 U301.6(DVDD)
N21723019: C314.1 U301.24(VDR2)
N21723038: C315.2 U301.23(BST2A)
N21723040: C315.1 C320.1 L302.1 L312.1 R306.2 R308.1 U301.18(OUT2B) U301.21(OUT2A)
N21723161: C319.2 R306.1
N21723167: T301.1(TP) U301.13(MONITOR_0)
N21723169: R307.2 U301.14(MONITOR_1)
N21723171: T302.1(TP) U301.15(MONITOR_2)
N21723173: C320.2 U301.16(BST2B)
N21723285: C321.2 R308.2
N21723435: FB302.1 J804.1
N21723437: FB301.1 J804.2
N21723451: FB303.2 J804.4
N21723475: FB304.2 J804.3
N21723494: C325.2 C334.1 L303.1 L313.1 R313.2 R317.1 U302.30(OUT1B) U302.33(OUT1A)
N21723515: C351.2 R327.2 U302.38(BCK)
N21723601: C328.2 R313.1
N21723605: C325.1 U302.35(BST1A)
N21723639: R314.1 U302.37(AD)
N21723713: C329.2 R317.2
N21723762: C332.2 U302.2(VDD_PLL)
N21723903: C334.2 U302.28(BST1B)
N21723921: C335.1 U302.27(VDR1)
N21723965: C342.1 U302.6(DVDD)
N21723986: C338.1 U302.24(VDR2)
N21724005: C339.2 U302.23(BST2A)
N21724007: C339.1 C344.1 L304.1 L314.1 R322.2 R324.1 U302.18(OUT2B) U302.21(OUT2A)
N21724126: C343.2 R322.1
N21724132: T303.1(TP) U302.13(MONITOR_0)
N21724134: R323.2 U302.14(MONITOR_1)
N21724136: T304.1(TP) U302.15(MONITOR_2)
N21724138: C344.2 U302.16(BST2B)
N21724244: C345.2 R324.2
N21727322: J812.2 T1.4
N21727332: J812.1 T1.3
N21735247: UNK4C26.2 UNK4U9.K2
N21735401: UNK4R17.2 UNK4U9.R5
N21775203: J813.1 UNK5R71.1
N21775223: J813.2 UNK5R72.1
N21775243: J813.4 UNK5R73.1
N21775263: J813.5 UNK5R74.1
N21775283: J813.6 UNK5R75.1
N21778072: T109.1(TP) U1.A4(GPIOX_0//SDIO_D0//JTAG_TDO)
N21778081: T110.1(TP) U1.B5(GPIOX_1//SDIO_D1//JTAG_TDI)
N21778090: T111.1(TP) U1.B2(GPIOX_2//SDIO_D2//UART_RX_AO_A)
N21778099: T112.1(TP) U1.A2(GPIOX_3//SDIO_D3//UART_TX_AO_A)
N21778148: T113.1(TP) U1.A3(GPIOX_4//SDIO_CLK//JTAG_CLK)
N21778157: T114.1(TP) U1.B3(GPIOX_5//SDIO_CMD//JTAG_TMS)
N21778166: T115.1(TP) U1.A1(GPIOX_6)
N21778175: T116.1(TP) U1.C3(GPIOX_7)
N21778255: T120.1(TP) U1.B10(GPIOX_11//UART_RTS_EE_A//PWM_D)
N21800110: R225.1 R226.1 T310.1(TP)
N21860313: C252.2 R228.2 U201.8(WCK)
N21864534: C254.2 R230.2 U202.8(WCK)
N21877006: C350.2 R326.2 U301.8(WCK)
N21880362: C352.2 R328.2 U302.8(WCK)
N21888872: Q3.3(COLLECTOR) R16.2 R17.2
N21888995: Q2.3(COLLECTOR) R18.2 R19.2
N21888998: Q2.1(BASE) R16.1
N21889394: Q3.1(BASE) R15.1
N21890397: Q4.3(COLLECTOR) R329.2 R332.2
N21890399: Q5.3(COLLECTOR) R330.2 R331.2
N21890429: Q5.1(BASE) R332.1
N21890459: Q4.1(BASE) R333.1
N21892579: R343.1 U1.G15(GPIOA_8//TDMB_SCLK//TDMB_SLV_SC)
N21892587: R344.1 U1.F17(GPIOA_9//TDMB_FS//TDMB_SLV_FS)
N21892603: R103.1 U1.F16(GPIOA_10//TDMB_DOUT0//TDMB_DIN0)
N21892620: R104.1 U1.F15(GPIOA_11//TDMB_DOUT1//TDMB_DIN1)
N21892674: R107.1 U1.H16(GPIOA_2//TDMC_SCLK//TDMC_SLV_SC)
N21892682: R108.1 U1.G17(GPIOA_3//TDMC_FS//TDMC_SLV_FS//)
N21892690: R109.1 U1.G16(GPIOA_4//TDMC_DOUT0//TDMC_DIN0/)
N21892698: R110.1 U1.G14(GPIOA_5//TDMC_DOUT1//TDMC_DIN1/)
N22017810: J814.2(D-) UNK5R84.1
N22017884: J814.4(ID) UNK5R83.1
N22060831: J814.3(D+) UNK5R85.1
N22093750: C263.2 C264.1 R233.2
N22093974: C265.2 C266.1 R234.1
N22094186: C267.2 C268.1 R235.2
N22094236: C269.2 C270.1 R236.1
N22099090: C361.2 C362.1 R339.2
N22099146: C363.2 C364.1 R340.1
N22099525: C365.2 C366.1 R341.2
N22099581: C367.2 C368.1 R342.1
N22143757: C5.1 U2.1(BS)
N22143759: C5.2 L1.1 U2.3(SW)
N22143887: R21.2 U2.8(RT)
N22143889: C10.1 R10.1 R11.2 U2.5(FB)
N22143938: C24.2 C25.2 U2.6(COMP)
N22143998: C24.1 R22.2

Pads without a net: NOREF#2 1; NOREF#3 1; NOREF#14 1; NOREF#20 1; NOREF#22 1; NOREF#28 1; NOREF#35 1; NOREF#36 1; NOREF#44 1; NOREF#49 1; NOREF#50 1; NOREF#51 1; NOREF#52 1; NOREF#53 1; T330 1; U1 N12 N13 N14; U54 4; U55 4; UNK3U1 J1 J9 L1 L9; UNK4U5 3 4 5 10 11 14 15 20 21 22 26 35 47; UNK4U9 A4 A6 A9 A11 AA1 AA2 AA7 AA8 AA9 AA10 AA11 AA12 AA13 AA14 AE1 AE14 AG2 AG13 AH4 AH6 AH9 AH11 B2 B13 D1 D14 H1 H2 H7 H8 H9 H10 H11 H12 H13 H14 J1 J7 J8 J9 J10 J11 J12 J13 J14 K1 K3 K5 K7 K8 K9 K10 K11 K12 K13 K14 L1 L2 L3 L4 L12 L13 L14 M1 M2 M3 M5 M8 M9 M10 M12 M13 M14 N1 N2 N3 N10 N12 N13 N14 P1 P2 P3 P10 P12 P13 P14 R1 R2 R3 R12 R13 R14 T1 T2 T3 T12 T13 T14 U1 U2 U3 U6 U7 U10 U12 U13 U14 V1 V2 V3 V12 V13 V14 W1 W2 W3 W7 W8 W9 W10 W11 W12 W13 W14 Y1 Y3 Y6 Y7 Y8 Y9 Y10 Y11 Y12 Y13 Y14

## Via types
v1: diameter 0.45, hole 0.25, TOP to BOTTOM, 1272 vias
v2: diameter 0.4, hole 0.2, TOP to BOTTOM, 429 vias
v3: diameter 0.508, hole 0.254, TOP to BOTTOM, 9 vias
v4: diameter 0.66, hole 0.406, TOP to BOTTOM, 2 vias

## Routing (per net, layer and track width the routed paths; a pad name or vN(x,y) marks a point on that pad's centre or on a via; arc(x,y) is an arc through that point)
5V_EN: length 86.4
  TOP w0.1: v1(70.84,15.5) 71.24,15.9 71.85,15.9 72.45,16.5 79.55,16.5 81.6,14.45 81.6,13.2 82.1,12.7 v1(83.1,12.7) ; v1(59.9,16.5) 59.75,16.5 59.3,16.95 59.3,17.52 53.65,23.17 53.65,23.55 53.4,23.8 52.6,23.8 v1(52.2,24.2)
  TOP w0.25: v1(13.45,19.5) 12.87,18.91 U2.7
  BOTTOM w0.1: UNK5R73.2 v1(83.1,12.7) ; v1(52.2,24.2) 52.1,24.2 50.9,25.4 42.15,25.4 40.8,24.05 38.65,24.05 37.5,25.2 35.95,25.2 35.25,24.5 32.9,24.5 30.25,21.85 29.65,21.85 27,19.2 19.45,19.2 18.85,18.6 C12.2 R2.1 R2.2 ; v1(59.9,16.5) 60.3,16.1 70.04,16.1 70.64,15.5 v1(70.84,15.5) ; R2.2 R3.2 15.95,18.5 14.55,19.9 13.85,19.9 v1(13.45,19.5) ; R2.2 16.95,17.2 17.15,17 R1.1
GND: length 2639.8
  TOP w0.1: v2(67.22,41.99) v2(67.22,42.64) ; v2(65.92,42.64) 65.27,42.64 ; 65.27,42.64 65.27,43.3 ; 65.27,42.64 v2(64.62,42.64) ; 93.5,26.55 v1(93.45,26.5) ; 62.01,41 62.01,41.32 62.03,41.34 ; 51.9,52.75 53.25,52.75
  TOP w0.102: 65.9,49.81 65.9,50.31 66.24,50.65 U1.A14 ; 59.99,38.85 60.07,38.93 60.07,40.7 ; UNK3U1.J2 58.46,29.14 59.43,29.14 ; 59.41,50.45 v2(59.41,50.45) 59.41,50.45 ; 59.41,50.45 59.41,51.67 v2(59.46,51.72) ; 65.91,44.59 v2(65.92,44.59) ; 65.91,44.59 65.91,44.59 65.92,44.58 v2(65.92,44.59) ; 65.91,44.59 65.91,44.6 v2(65.92,44.59) ; U1.M17 68.01,43.62 67.69,43.94 v2(67.22,43.94) ; v2(62.1,41.41) 62.03,41.34 61.58,41.34 61.36,41.12 61.36,40.89 61.04,40.57 U1.U6 ; v2(62.2,38.81) 62.05,38.97 62.05,40.6 62.01,40.64 62.01,41 ; v2(65.66,27.26) 66.62,27.26 67.59,28.22 ; v2(66.42,26.34) 66.85,26.34 67.59,27.08 67.59,27.51 ; 63.16,38.06 v2(63.24,38.17) 63.07,38.34 63.07,39.11 62.69,39.49 62.69,40.54 63.01,40.87 63.01,41 U1.T9 ; 63.16,38.06 63.16,37.56 63.62,37.09 64.49,37.09 v2(64.62,36.96) ; 63.16,38.06 63.24,38.15 ; v2(65.48,38.08) 65.47,38.09 65.47,38.3 64.77,39 64.25,39 63.97,39.29 63.97,39.57 v2(63.7,39.88) ; v2(66.24,38.36) 65.89,38.71 65.71,38.71 64.92,39.5 64.92,39.73 64.62,40.03 64.62,40.7 ; 64.92,43.64 64.62,43.33 v2(64.62,42.64) ; v2(56.74,41.53) 57.2,41.99 58.11,41.99 U1.P2 ; U1.F3 58.75,47.86 58.29,47.86 58.09,48.06 57.39,48.06 55.66,49.79 v2(55.37,49.79) ; 56.67,28.25 56.67,28.27 56.74,28.35 57.68,28.35 v2(57.73,28.4) ; 56.67,28.25 56.67,28.22 ; 56.67,28.25 v2(56.59,28.15) ; v2(59.99,37.19) 59.99,36.88 60.63,36.25 60.63,30.88 60.61,30.86 60.61,30.79 ; v2(62.45,29.14) 60.11,29.14 v2(60.01,29.24) ; v2(66.01,39.65) 66,39.66 ; 58.77,46.54 58.77,45.49 58.76,45.49 v2(58.76,45.24) v2(59.41,45.24) ; 58.77,46.54 58.32,46.54 58,46.22 U1.H1 ; 58.77,46.54 58.77,47.2 ; U1.J17 67.97,45.57 67.64,45.9 67.21,45.9 U1.H15 ; U1.P8 U1.R8 ; v2(60.06,49.15) v2(60.06,49.8) ; 55.98,33.96 57.41,33.96 57.64,33.73 57.64,32.34 ; 61.01,31.55 v2(62.46,31.55) ; v2(61.19,37.19) 61.19,36.97 61.52,36.64 61.52,34.91 v2(61.69,34.74) ; 57.74,34.06 57.63,33.96 v2(57.63,33.94) ; v2(59.54,26.11) 59.36,25.94 v2(58.44,25.94) 58.44,25.35 58.21,25.12 57.79,25.12 57.4,24.73 UNK3U1.P1 57.66,24.32 57.66,23.52 ; v2(66.57,40.69) 66.57,40.7 ; U1.K2 58.12,44.6 57.64,44.6 57.41,44.38 v2(56.08,44.38) ; v2(76.58,46.87) 74.92,46.87 74.28,46.23 69.29,46.23 68.97,46.55 v2(67.22,46.55) ; v2(57.9,39.88) 58.11,40.09 58.11,40.52 58.29,40.69 58.57,40.69 58.76,40.88 v2(58.76,41.35) 58.24,41.35 57.92,41.02 U1.T1 ; 64.87,28.34 64.91,28.2 65.61,28.2 v2(65.99,28.58) ; 65.92,43.29 65.92,43.08 65.92,43.08 v2(65.92,42.64) ; v2(58.8,37.06) 58.8,36.79 59.74,35.85 59.74,32.29 59.35,31.89 v2(59.35,31.65) 59.22,31.52 58.46,31.52 UNK3U1.E2 ; v2(63.28,30.7) 63.28,30.77 ; 62.66,42.64 62.64,42.64 ; 66.58,42.65 66.57,42.64 66.58,42.65
  TOP w0.127: v2(65.5,30.09) 65.41,30.01 64.95,29.55 64.95,29.63 v2(64.87,29.56)
  TOP w0.14: v2(62.45,32.34) 62.46,32.34 61.01,32.34
  TOP w0.15: v2(58.11,42.64) 58.11,42.65 56.81,42.65 v2(56.69,42.52)
  TOP w0.152: v2(58.47,33.96) 58.46,33.94 57.86,33.94 57.47,34.34 57.25,34.34 ; v2(64.87,29.56) 64.87,28.34 63.25,28.34
  TOP w0.2: UNK4U9.M7 43.51,42.71 43.8,43 ; v1(38.2,14) 37.8,13.6 37.8,10.8 ; v1(33.65,54) 33.65,53.8 34.15,53.3 34.15,23.55 36.55,21.15 36.55,4.1 37.85,4.1 38,4.25 ; 37.8,10.8 U52.2 ; 37.8,10.8 37.8,6.7 ; 83.1,57.4 83.05,57.45 83.05,58.8 83.1,58.85 ; 69.05,22.95 69.24,22.76 v2(69.24,22.76) ; 37.8,6.7 v1(38.15,6.35) v1(39.2,6.35) 39.2,5.8 38.9,5.5 38.3,5.5 v1(38,5.2) 37.8,5.4 37.8,6.7 ; UNK2Q1.2 59.25,62.95 62.4,62.95 ; C62.2 45.93,17.53 C61.1 45.28,14.03 45,13.75 v1(45,13.4) ; 62.4,62.95 64.45,62.95 64.5,63 66.1,63 v2(67.15,61.95) UNK2C15.1 ; 62.4,62.95 v1(62.4,62.45) ; v1(34.85,23.85) 34.85,23.65 37.05,21.45 37.05,5.2 38,4.25 ; v1(52.12,54.36) 52.19,54.36 52.7,53.85 53.39,53.85 ; v2(72.36,44.63) 72.92,44.63 73.65,43.9 73.65,43.3 73.8,43.15 75.6,43.15 v2(75.6,42.55) ; 38,4.25 42.85,4.25 C67.1 ; 58.01,60.96 58.01,59.86 57.85,59.7 57.85,56.25 v2(58.01,56.09) ; 35.95,25.15 35.9,25.2 ; UNK4U9.Y5 UNK4U9.AA6
  TOP w0.25: U1.L9 62.97,44.27 62.67,43.98 v2(62.62,43.98) ; 45.99,52.99 45.64,52.64 UNK4U5.33 45.64,50.29 45.4,50.05 44.14,50.05 ; R7.1 31.91,5.09 v1(31.9,5.1) ; U1.N6 61.04,42.97 v2(61.36,42.64) U1.N7 61.69,42.97 v2(62.01,42.64) 62.34,42.32 U1.P8 ; 49.14,32.84 UNK4U5.23 49.14,30.44 ; v1(39.3,49.8) 39.14,49.96 UNK4U5.46 ; v2(60.07,43.92) 60.04,43.92 U1.M4 ; U1.L8 62.34,44.26 v2(62.62,43.98) ; UNK4U5.27 48.64,52.19 UNK4C11.1 ; U1.M4 59.46,43.34 ; U1.M4 59.42,43.95 U1.L4 ; 65.27,44.6 U1.K12 ; U1.K12 65.27,45.24 65.27,45.24 U1.K13 ; U1.K12 v2(64.62,45.24) U1.J11 ; U1.K12 64.62,44.6 v2(64.62,44.59) 64.29,44.27 U1.L11 ; 38.1,52.35 38.14,52.31 UNK4U5.48 38.14,49.86 v1(38.2,49.8) ; 38.64,30.26 UNK4U5.2 38.64,32.74 ; v2(66.42,26.34) v2(64.11,26.34) 64.1,26.33 UNK3U1.M9 ; 44.14,50.05 42.4,50.05 42.14,50.31 UNK4U5.40 42.14,52.96 41.86,53.24 41.86,55.05 v1(41.28,55.05) UNK4R52.1 ; 44.14,50.05 UNK4U5.36 44.14,51.97 ; v2(62.62,43.98) 62.98,43.62 U1.M9 ; 49.9,52.4 49.64,52.14 UNK4U5.25 49.64,50.06 ; 44.15,32.95 44.14,32.94 UNK4U5.13 44.14,30.46 v1(44.25,30.35) ; U1.M14 U1.N15 v2(67.22,42.64)
  TOP w0.254: U1.N3 59.09,42.97 ; U1.N3 59.09,42.97 ; U1.N3 59.1,42.96 ; U1.N3 59.09,42.97 ; U1.N3 59.09,42.97 ; 59.09,42.97 59.09,42.97 ; 59.09,42.97 59.09,42.97 ; 59.09,42.97 58.88,42.75 ; 59.09,42.97 59.09,42.97 ; 59.09,42.97 58.86,43.2 58.68,43.2 58.44,42.97 ; 59.09,42.97 59.09,42.97 ; 58.44,42.97 U1.N2 58.44,42.97 ; 58.44,42.97 58.76,42.65 ; 58.44,42.97 58.44,42.97 ; U1.L6 v2(61.36,43.94) ; U1.L6 60.88,44.43 ; U1.L6 60.88,44.43 ; U1.L6 60.88,44.43 ; U1.L6 v2(61.36,44.59) ; U1.L6 v2(61.36,43.94) ; U1.L6 60.71,43.94 ; v2(61.36,43.94) U1.L7 ; 64.62,43.94 v2(64.69,43.94) ; 64.62,43.94 U1.M12 65.27,43.94 ; 64.62,43.94 U1.L12 ; 64.62,43.94 U1.L11 v2(63.97,44.59) ; v2(63.97,44.59) 63.64,44.27 ; v2(63.97,44.59) U1.K10 ; 63.64,44.27 63.32,43.94 ; 63.64,44.27 63.32,44.59 ; U1.H7 62.01,45.9 ; U1.H7 61.36,45.9 ; U1.H7 v2(62.01,46.55) ; 62.01,45.9 U1.J8 ; 62.01,45.9 U1.J7 ; 62.01,45.9 U1.H8 ; 59.1,42.96 59.69,42.37 ; 59.1,42.96 59.09,42.97 ; 59.1,42.96 58.77,42.64 ; 59.69,42.37 U1.P4 ; 59.69,42.37 59.41,42.64 59.09,42.32 ; U1.P8 62.34,42.34 62.64,42.64 ; U1.R17 68.37,41.49 68.37,41.48 v2(69.06,41.48) ; 61.04,44.92 U1.K6 61.25,45.13 ; 61.04,44.92 60.72,44.59 ; 61.04,44.92 61.25,45.13 61.25,45.13 ; 61.04,44.92 v2(61.36,44.59) ; U1.A14 66.24,51.54 ; 66.24,51.54 66.24,52.85 66.57,53.18 ; 66.24,51.54 66.25,51.55 66.29,51.51 66.29,51.36 v2(66.3,51.36) ; U1.H14 v2(66.57,46.55) 66.88,46.23 U1.H15 ; U1.H14 U1.G13 ; U1.H14 66.56,45.9 ; U1.N9 63.32,43.29 ; U1.N9 v2(63.32,42.64) U1.N10 ; U1.N9 62.66,42.64 ; 63.32,43.29 U1.M9 63.32,43.94 ; 63.32,43.29 U1.N10 ; 61.19,39.52 61.04,40.01 U1.U6 ; v2(60.06,40.69) 60.07,40.7 U1.T5 ; U1.H8 62.66,45.9 ; U1.H8 v2(62.01,46.55) ; U1.H8 v2(62.66,46.55) ; 62.66,45.9 U1.J9 ; 62.66,45.9 U1.J8 ; 62.66,45.9 U1.H9 ; v2(61.39,45.21) 61.36,45.24 ; 61.36,45.24 61.25,45.13 ; 61.36,45.24 U1.K7 ; 61.36,45.24 U1.J7 ; 59.09,42.97 58.88,42.75 ; 63.32,47.85 63.15,48.01 ; 63.32,47.85 U1.F10 ; 63.32,47.85 U1.E10 ; 63.32,47.85 U1.F9 ; 63.32,47.85 v2(63.32,47.86) ; 63.15,48.01 U1.E9 ; 63.15,48.01 U1.E9 ; 63.97,46.55 U1.H11 ; 63.97,46.55 U1.G11 ; 63.97,46.55 U1.H10 ; 63.97,46.55 U1.G10 ; U1.H11 64.62,45.9 U1.J11 63.97,45.9 ; U1.H11 v2(64.62,46.55) ; U1.H11 63.97,45.9 ; 60.88,44.43 60.72,44.59 ; v2(62.66,49.15) 62.66,49.15 U1.D9 ; U1.J17 68.65,45.57 68.73,45.49 ; U1.J7 61.36,45.9 ; U1.J7 v2(62.01,45.24) ; 61.36,45.9 U1.H6 ; U1.K8 62.01,44.59 ; U1.K8 v2(62.01,45.24) ; U1.K8 62.66,44.59 ; U1.K8 v2(62.66,45.24) ; 62.01,44.59 U1.L8 ; 62.01,44.59 U1.L7 ; 62.01,44.59 U1.K7 ; 60.07,43.94 60.39,44.26 ; 60.07,43.94 v2(60.07,43.92) 60.08,43.93 ; 60.07,43.94 60.08,43.93 ; 60.07,43.94 U1.L4 ; 60.39,44.26 U1.L5 60.4,44.28 ; 60.39,44.26 60.4,44.28 ; 60.39,44.26 60.08,43.93 ; U1.J10 63.97,45.9 ; U1.J10 v2(63.32,45.24) ; U1.J10 63.32,45.9 ; 63.97,45.9 U1.H10 ; 63.32,46.55 U1.H10 ; 63.32,46.55 U1.G9 ; 63.32,46.55 U1.H9 ; 63.32,46.55 U1.G10 ; 63.32,46.55 v2(63.35,46.54) ; U1.H10 63.32,45.9 ; U1.J9 63.32,45.9 ; U1.J9 v2(62.66,45.24) ; U1.J9 v2(63.32,45.24) ; 63.32,45.9 U1.H9 ; U1.E5 60.71,48.49 v2(60.71,48.5) ; U1.E5 v2(60.06,48.5) ; U1.E5 v2(60.71,47.85) 60.72,47.85 U1.E6 ; U1.E5 60.06,47.85 ; U1.G9 63.32,47.2 ; U1.G9 v2(62.66,47.2) ; U1.G9 v2(62.66,46.55) ; 63.32,47.2 U1.F9 ; 63.32,47.2 v2(63.32,47.2) ; 63.32,47.2 U1.G10 ; 63.32,47.2 U1.F10 ; 66.58,42.65 66.89,42.97 U1.N15 66.57,42.65 66.57,42.64 66.24,42.32 U1.P14 v2(65.92,42.64) ; 62.66,44.59 U1.L9 ; 62.66,44.59 U1.L8 ; 62.66,44.59 v2(62.6,44.59) ; 62.66,44.59 U1.K9 ; U1.L9 63.32,44.59 ; U1.L9 63.32,43.94 ; 58.76,42.65 58.88,42.75 ; 58.76,42.65 U1.P3 ; 58.76,42.65 58.76,42.64 ; 58.88,42.75 58.77,42.64 58.76,42.64 ; 66.24,47.52 U1.F14 ; 66.24,47.52 U1.F14 ; 66.24,47.52 v2(66.57,47.85) ; U1.F14 v2(65.92,47.2) U1.G13 ; U1.F14 66.09,47.67 66.09,47.68 v2(65.91,47.86) 65.91,47.85 U1.E13 ; v2(64.62,48.5) U1.D12 65.27,48.5 ; v2(64.62,48.5) U1.E12 ; v2(64.62,48.5) U1.E11 ; v2(64.62,48.5) U1.E12 ; v2(60.06,48.5) 59.74,48.17 ; v2(60.06,48.5) 60.39,48.82 U1.D5 ; U1.E10 v2(63.97,48.5) 63.97,48.49 U1.E11 ; U1.E10 v2(63.32,48.5) ; U1.E10 63.97,47.85 ; v2(64.62,44.59) U1.L12 ; U1.L12 65.27,44.6 U1.K13 ; U1.L12 65.27,43.94 ; v2(62.01,48.5) U1.E8 ; v2(62.01,48.5) U1.E7 ; v2(62.01,48.5) U1.D7 ; U1.E8 v2(62.66,47.85) ; U1.E8 62.67,48.5 ; U1.E8 v2(62.01,47.85) ; U1.F10 63.97,47.2 ; U1.F10 63.97,47.85 ; U1.G8 v2(62.01,47.2) ; U1.G8 v2(62.66,46.55) ; U1.G8 62.18,46.71 ; U1.G8 v2(62.66,47.2) ; v2(62.01,47.2) U1.F8 ; v2(62.01,47.2) 61.85,47.36 ; v2(62.01,47.2) 61.85,47.36 ; v2(62.01,47.2) 61.69,46.87 U1.G7 v2(62.01,46.55) ; 59.09,41.67 58.77,41.99 ; 59.09,41.67 59.41,41.99 v2(59.41,41.99) ; 59.09,41.67 v2(58.76,41.35) ; 59.09,41.67 U1.R3 ; 58.77,41.99 U1.P2 ; 58.77,41.99 59.09,42.32 ; U1.G13 65.27,46.55 65.26,46.55 U1.G12 v2(64.62,46.55) ; v2(62.01,45.24) U1.K7 ; v2(62.01,45.24) U1.J8 ; v2(65.92,43.94) 66.24,43.62 ; v2(65.92,43.94) U1.M13 ; v2(65.92,43.94) 66.24,44.27 ; 66.24,43.62 v2(66.57,43.94) ; 66.24,43.62 66.24,43.62 U1.M14 ; 66.24,43.62 U1.M14 ; U1.M13 65.92,43.29 ; U1.M13 65.27,43.94 ; U1.B17 68.73,50.12 v2(68.73,50.04) ; 66.56,45.9 U1.J14 U1.K13 ; 66.56,45.9 U1.H15 ; U1.H15 v2(67.22,46.55) ; 60.72,44.59 U1.K5 60.07,45.24 v2(60.06,45.24) ; 60.72,44.59 60.4,44.28 ; v2(62.66,46.55) U1.H9 ; v2(59.41,47.85) 59.41,47.84 U1.F3 58.77,47.2 ; v2(59.41,47.85) U1.F4 60.06,47.85 ; v2(59.41,47.85) 59.74,48.17 ; 65.72,44.79 v2(65.92,44.59) ; 65.72,44.79 U1.K13 ; 65.72,44.79 v2(65.92,44.59) ; v2(59.41,50.45) U1.B4 v2(60.06,49.8) ; 66.57,40.7 U1.T15 ; v2(62.01,46.55) 62.18,46.71 ; v2(62.01,46.55) 62.18,46.71 ; U1.E13 v2(65.97,48.55) U1.D14 66.3,48.88 v2(66.01,49.18) ; U1.E13 65.27,48.5 ; U1.E13 65.27,47.85 U1.E12 ; 58.76,42.64 58.77,42.64 ; 58.76,42.64 U1.P2 ; 58.76,42.64 58.44,42.97 ; U1.M5 U1.N6 v2(60.71,42.64) ; U1.M5 60.71,43.94 ; U1.M5 60.08,43.93 ; 60.71,43.94 60.4,44.28 ; U1.G11 64.61,46.55 v2(64.62,46.55) ; U1.G11 63.97,47.2 ; U1.U3 59.09,40.37 59.09,39.66 58.8,39.37 v2(58.8,39.27) ; U1.K7 v2(61.36,44.59) ; 65.92,43.29 65.92,43.3 U1.M14 ; 65.92,43.29 U1.M14 ; 58.77,42.64 U1.P2 ; 58.77,42.64 59.09,42.32 ; v2(62.86,51.62) 62.96,51.51 62.96,50.77 U1.A9 ; 59.74,48.17 v2(59.41,48.5) ; 59.74,48.17 59.74,48.17 ; 59.74,48.17 U1.E4 ; U1.F9 v2(62.66,47.85) ; U1.F9 62.67,47.2 v2(62.66,47.2) ; U1.F8 v2(62.66,47.2) ; U1.F8 v2(62.01,47.85) ; U1.F8 62.5,47.68 ; U1.F8 62.5,47.68 ; U1.L8 62.02,43.95 62.01,43.95 U1.L7 ; U1.E7 v2(62.01,47.85) ; U1.E7 v2(61.36,48.5) ; U1.E7 61.36,47.85 U1.F7 ; v2(63.7,39.88) 63.67,39.87 63.67,40.37 U1.U10 ; v2(66.57,43.94) 66.57,43.95 U1.L15 v2(67.22,43.94) ; v2(66.57,43.94) 66.24,44.27 ; U1.N10 v2(63.97,42.64) U1.P11 ; 65.27,48.5 U1.E12 ; U1.J8 v2(62.66,45.24) ; v2(62.66,45.24) U1.K9 ; 65.8,39.87 65.8,39.92 65.76,39.96 65.76,40.01 65.59,40.19 U1.U13 ; 63.97,47.2 U1.F11 ; 63.97,47.2 v2(63.96,47.2) ; 63.97,47.2 U1.G10 ; U1.F11 64.62,47.85 ; U1.F11 63.97,47.85 ; v2(63.32,48.5) U1.D9 ; v2(63.32,48.5) U1.E9 ; v2(62.66,47.85) 62.5,47.68 ; v2(62.66,47.85) U1.E9 ; 56.77,40.07 56.77,40.21 57.58,41.02 U1.T1 ; 66.24,44.27 U1.L14 ; 66.24,44.27 U1.L14 ; U1.L14 v2(65.92,44.59) ; 45.99,52.99 UNK4C10.1 45.99,54.33 v1(46.55,54.33) ; U1.E11 63.97,47.85 ; U1.E11 64.62,47.85 ; 63.97,47.85 v2(63.96,47.86) ; v2(59.41,41.99) U1.P4 ; v2(59.41,41.99) 59.09,42.32 ; v2(65.92,44.59) 65.91,44.59 ; v2(60.71,48.5) U1.E6 ; v2(60.71,48.5) U1.D5 ; U1.K10 v2(63.32,45.24) ; U1.K10 63.32,44.59 ; 64.62,47.85 U1.E12 ; U1.E6 v2(61.36,48.5) ; U1.E6 U1.F7 ; 60.06,47.85 U1.E4 ; U1.T9 62.99,41.02 v2(63.28,41.32) ; U1.D9 62.67,48.5 ; U1.K9 63.32,44.59 ; U1.K9 v2(63.32,45.24) ; v2(63.97,41.99) v2(64.62,42.64) ; U1.E9 62.67,48.5 ; U1.M17 68.65,43.62 68.86,43.49 v2(68.91,43.44) ; U1.L7 v2(61.36,44.59) ; U1.P4 v2(60.06,41.99) ; 62.67,48.5 v2(62.66,48.5) ; v2(61.36,48.5) U1.D7 ; 61.85,47.36 U1.F7 ; U1.F7 v2(62.01,47.85) ; 44.14,51.97 44.4,52.22 v1(44.4,52.73) ; U1.D7 v2(61.36,49.15) ; v2(64.67,40.74) 64.62,40.7 U1.T12 ; U1.U16 67.54,40.06 68.02,39.58 v2(68.02,39.55) ; 65.27,43.94 v2(65.25,43.94) ; U1.D5 v2(60.06,49.15) ; v2(58.76,45.24) U1.K2 ; U1.E4 59.74,48.17
  TOP w0.3: 42.01,37.7 UNK4U9.AA4 ; 41.83,54.48 UNK4R52.1 40.73,54.48 ; C7.2 21.7,2.3 ; C7.2 20.75,2.95 ; C7.2 20.75,1.65 ; C7.2 19.8,2.3 ; 27.66,6.59 R9.1 28.21,6.09 ; 73.01,52.91 UNK2Y2.4 73.91,52.11 ; U1.N3 59.09,42.97 v2(59.46,43.33) 59.46,43.34 ; C104.1 73.4,46.8 ; C2.2 76.65,15.1 ; C2.2 75.95,14.55 ; C2.2 C1.2 ; C9.1 23.05,3 ; C9.1 21.95,3 ; C9.1 22.5,2.5 ; 27.46,10.04 U3.2 28.96,10.04 ; U1.L13 65.59,44.27 v2(65.92,44.59) ; U1.L13 65.26,43.94 v2(65.25,43.94) ; U1.L13 v2(65.92,43.94) ; U1.L13 65.27,44.6 ; C62.2 45.93,19.36 ; C62.2 45.28,18.41 ; C62.2 46.58,18.41 ; 44.01,40.5 UNK4U9.U8 44.01,39.7 ; 35.75,62.95 35.75,62.35 35.12,61.73 33.48,61.73 32.5,60.75 32.5,52.4 32.3,52.2 32.3,51 32.95,50.35 32.95,38.55 v1(32.55,38.15) 32.55,37.65 32.3,37.4 31.75,37.4 31.35,37.8 31.35,38.4 32.25,39.3 v1(32.25,49.21) 32.25,49.7 31.7,50.25 31.7,52.55 31.9,52.75 31.9,57.85 31.1,58.65 v1(31.1,61) 31.1,61.65 32.45,63 35.7,63 35.75,62.95 ; 35.75,62.95 35.8,63 36.85,63 37.4,62.45 37.4,62.25 37.15,62 36.3,62 34.85,60.55 34.85,59.55 33.6,58.3 33.6,55.3 33.65,55.25 ; 54.35,12.5 C68.2 ; C68.2 56.25,12.5 ; C68.2 55.3,11.85 ; U1.K4 59.74,44.92 v2(60.06,45.24) ; U1.K4 59.42,45.24 v2(59.41,45.24) ; U1.K4 59.98,44.68 v2(60.04,44.68) ; C60.2 46.58,20.34 ; C60.2 45.93,19.39 ; C60.2 45.93,21.29 ; C60.2 45.28,20.34 ; 56.63,17.59 C71.2 ; C71.2 55.98,18.54 ; C71.2 56.63,19.49 ; C71.2 57.28,18.54 ; v1(43,45.45) 43.01,45.44 ; 56.63,15.66 C73.2 ; C73.2 57.28,16.61 ; C73.2 55.98,16.61 ; C73.2 56.63,17.56 ; C353.2 28.7,35.5 ; C353.2 27.95,34.4 ; C353.2 27.95,36.6 ; v2(66.57,49.8) 66.01,49.24 v2(66.01,49.18) ; v2(57.61,22.77) 57.25,23.13 UNK3U1.T1 57.26,23.13 57.66,23.52 ; 33.65,55.25 34.05,55.65 34.85,55.65 35.35,55.15 35.35,25.75 35.9,25.2 ; 33.65,55.25 33.65,54.45 ; UNK4K2.1 1.47,17.49 ; UNK4K2.1 0.82,16.79 ; UNK4K2.1 2.12,16.79 ; UNK4K2.1 1.47,16.09 ; C355.2 28.7,57.45 ; C355.2 27.95,56.35 ; C355.2 27.95,58.55 ; 54.85,72.6 UNK2CON1.1 54.85,70.4 ; v2(64.21,23.14) 64.2,23.13 UNK3U1.T9 ; v1(45.5,41.1) UNK4U9.R10 v1(44,41.1) ; v1(45.5,41.1) v1(45.5,42.95) ; v1(45.5,41.1) v1(45.5,39.65) 44.01,39.65 ; 17.6,2.3 C6.2 ; C6.2 19.5,2.3 ; C6.2 18.55,1.65 ; C6.2 18.55,2.95 ; 75.55,41.45 UNK5R78.2 75.05,40.9 ; C13.2 34.31,12.39 ; C13.2 34.31,11.09 ; C13.2 33.36,11.74 ; C13.2 35.26,11.74 ; 56.8,34.33 UNK3U1.B1 ; 34.99,19.58 C16.2 ; C16.2 35.64,20.53 ; C16.2 36.29,19.58 ; C16.2 35.64,18.63 ; C356.2 27.95,49.75 ; C356.2 27.95,47.55 ; C356.2 28.7,48.65 ; v1(99.99,54.1) 108.7,54.1 ; 49.7,52.75 UNK4C11.1 49.2,53.3 ; 89.1,48.55 C255.2 ; C255.2 89.1,50.75 ; C255.2 88.35,49.65 ; 83.75,36.6 v1(83.8,36.55) 83.9,36.45 83.9,25.65 v1(84.5,25.05) ; v2(57.73,28.4) 57.73,28.41 UNK3U1.J2 ; v2(62.46,31.55) 62.47,31.55 UNK3U1.E8 62.45,32.33 v2(62.45,32.34) 62.46,32.34 UNK3U1.D8 ; 42.91,41.6 UNK4U9.P5 42.25,41.6 v1(42,41.85) v1(42,42.6) 42,43.59 UNK4U9.K4 ; UNK4U9.H6 43.01,45 ; 88.35,36.5 C258.2 ; C258.2 89.1,35.4 ; C258.2 89.1,37.6 ; UNK2D3.2 55.05,65.71 ; UNK2D3.2 54.4,65.21 ; UNK2D3.2 55.05,64.71 ; UNK2D3.2 55.7,65.21 ; R11.1 17.9,18.85 ; R11.1 17.35,19.35 ; R11.1 16.8,18.85 ; UNK2Y2.2 77.11,51.16 ; UNK2Y2.2 76.21,51.97 ; UNK2Y2.2 76.21,50.36 ; UNK3U1.B3 58.84,34.33 v2(58.47,33.96) ; 64.4,65.21 UNK2D4.2 63.75,64.71 ; 9.8,17.05 R21.1 ; R21.1 10.35,17.55 ; R21.1 9.25,17.55 ; 88.35,58.45 C256.2 ; C256.2 89.1,59.55 ; C256.2 89.1,57.35 ; 57.25,31.94 57.25,31.94 v2(57.64,32.34) UNK3U1.E2 ; 57.25,31.94 UNK3U1.E1 ; 57.25,31.94 v2(56.84,32.35) ; UNK3U1.G9 64.1,30.33 ; v2(60.71,42.64) U1.P5 v2(60.06,41.99) ; UNK4U5.25 50.02,51.15 ; v2(76.58,42.8) 77,43.22 77,44.35 v2(76.65,44.35) 74.2,44.35 v2(74,44.55) ; 43.01,37.7 UNK4U9.AA6 ; C18.2 35.64,18.6 ; C18.2 34.99,17.65 ; C18.2 35.64,16.7 ; C18.2 36.29,17.65 ; C20.1 31.91,7.59 ; C20.1 31.91,6.49 ; C20.1 31.41,7.04 ; 7.47,16.09 UNK4K2.2 ; UNK4K2.2 8.12,16.79 ; UNK4K2.2 6.82,16.79 ; UNK4K2.2 7.47,17.49 ; UNK2Q1.2 59.85,63.5 ; UNK2Q1.2 59.25,64.1 ; UNK2Q1.2 58.65,63.5 ; v2(62.45,29.14) 62.85,28.74 UNK3U1.J8 63.24,28.34 63.25,28.34 ; 48.2,33.9 47.95,33.65 46.65,33.65 45.95,32.95 v1(42.65,32.95) ; 56.8,32.73 UNK3U1.D1 ; 34.99,15.57 C17.1 ; C17.1 34.99,16.67 ; C17.1 35.49,16.12 ; 42.55,11.7 C58.1 ; C58.1 43.65,11.7 ; C58.1 43.1,12.2 ; v2(63.28,30.7) 63.22,30.7 UNK3U1.G8 ; 11.45,9.4 C4.2 10.9,10.1 ; 44.6,11.85 C57.2 ; C57.2 43.65,12.5 ; C57.2 45.55,12.5 ; C57.2 44.6,13.15 ; 48.45,10.8 U53.2 49.95,10.8 ; v1(82.5,29) 82.5,32.65 81.8,33.35 81.8,47.6 ; 38.17,54.48 UNK4R2.1 37.62,54.98 ; U1.M12 65.26,43.3 U1.M13 ; C69.1 53.8,12.2 ; C69.1 54.35,11.7 ; C69.1 53.25,11.7 ; UNK4R13.1 38.84,54.98 ; UNK4R13.1 39.39,54.48 ; UNK4R13.1 38.29,54.48 ; v2(70.71,43.66) 71.68,43.66 UNK5C11.1 ; C61.1 45.28,17.43 ; C14.1 32.81,11.44 ; C14.1 33.36,10.94 ; C14.1 32.26,10.94 ; C72.1 56.48,15.08 ; C72.1 55.98,15.63 ; C72.1 55.98,14.53 ; 48.25,29.7 UNK4C4.1 ; UNK4C4.1 48.75,29.15 ; UNK4C4.1 48.75,30.25 ; C354.2 27.95,27.8 ; C354.2 28.7,26.7 ; C354.2 27.95,25.6 ; 89.1,26.6 C257.2 ; C257.2 89.1,28.8 ; C257.2 88.35,27.7 ; v2(62.1,41.41) 62.1,41.43 U1.R8 ; v1(84.75,57.89) 84.6,58.04 84.6,59.35 85.35,60.1 85.35,60.8 84.95,61.2 84.25,61.2 v1(84.25,60.8) 84.25,60.25 84,60 84,56.35 ; 39.8,38.2 40.2,38.6 UNK4U9.Y2 ; 53.75,7.9 C75.1 53.2,8.4 ; U52.2 39.25,10.8 ; v2(56.08,44.38) 55.77,44.38 55.6,44.55 51.98,44.55 UNK4C3.1 51.04,43.79 49.5,42.25 49.5,36.35 47.45,34.3 46.4,34.3 45.85,33.75 42.35,33.75 41.7,33.1 v1(41.7,32.95) ; UNK3U1.M1 56.74,26.33 v2(56.73,26.34) ; 33.65,54.45 34.45,54.45 34.75,54.15 34.75,23.95 v1(34.85,23.85) ; 33.65,54.45 v1(33.65,54) ; 71.45,43.4 UNK5C11.1 ; UNK5C11.1 71.95,42.85 ; v1(99.95,32.1) 108.7,32.1 ; UNK5C3.1 v2(75.6,42.55) ; 66.3,48.88 v2(66.57,49.15) 65.9,49.81 ; UNK4C5.2 40.1,29.3 ; UNK4C5.2 39.55,30 ; UNK4C5.2 39.55,28.6 ; UNK4C10.1 46.49,53.62 ; v2(63.52,35.54) 63.65,35.41 UNK3U1.A9 UNK3U1.B9 ; v2(60.04,44.68) 60.15,44.68 U1.K5 ; v2(60.04,44.68) 60.04,44.62 U1.L5 ; C67.1 43.35,6.75 ; UNK4U9.T5 42.91,40.6 ; 43.51,42.2 UNK4U9.M7 ; v1(15.05,31.1) 8.3,31.1 ; 52.75,8.25 R63.1 52.25,8.8 ; C1.2 78.75,14.55 ; C1.2 78.05,15.1 ; v3(66.34,54.79) 66.64,55.09 UNK2R14.2 ; 72.26,51.57 UNK2C9.1 ; U1.N2 v2(58.11,42.64) 58.12,42.64 U1.P2 ; UNK2U2.1 66.03,58.88 67.15,60 UNK2C15.1 66.65,60.25 ; 42.85,8.4 R60.1 43.35,7.85 ; 32.76,4.59 R7.1 ; 15.51,13.8 U2.4 16.26,12.85 ; UNK3U1.F9 64.1,31.13 ; v1(15.15,53.05) 7.35,53.05 ; UNK2C3.1 72.76,50.98 ; UNK4U5.36 44.14,52.2
  TOP w0.305: v3(66.34,54.79) 66.25,54.79 65.2,53.74 65.2,51.54 v2(65.06,51.4) ; v2(64.17,31.13) 64.17,31.14 63.65,31.14 63.28,30.77 ; v2(64.13,30.33) 63.65,30.34 63.64,30.34 v2(63.28,30.7) ; v2(56.84,32.35) 57.23,32.74 57.25,32.74 57.64,32.34 v2(57.64,32.34)
  TOP w0.356: v2(73.84,54.43) 73.12,54.43 72.6,53.91 v2(72.24,53.91)
  TOP w0.381: 57.25,34.34 v2(56.89,34.67)
  TOP w0.4: v2(64.22,24.73) 64.21,24.73 UNK3U1.P9 ; 72.27,51.55 72.27,52.12 ; 72.27,51.55 v2(72.85,51.55) ; 72.27,51.55 72.26,51.55 UNK2C3.1 ; 72.27,52.12 UNK2C9.1 ; 72.27,52.12 v2(72.85,52.7) 73.69,52.7 UNK2Y2.4 74.19,52.91 v2(74.95,52.15) 75.94,51.16 UNK2Y2.2 ; UNK3U1.P1 56.7,24.73 v2(56.69,24.74) ; v2(56.7,30.42) 56.79,30.33 UNK3U1.G1 ; v1(62.8,1) 62.5,0.7 51.5,0.7 v1(51.45,0.75) 51.4,0.7 3.2,0.7 2.7,1.2 v1(1.25,1.2)
  TOP w0.406: v2(61.19,39.83) v2(61.19,38.41) v2(61.19,37.19) ; v2(63.24,38.17) 63.24,38.15 ; v2(76.6,54) 76.05,54 75.61,54.43 v2(75.38,54.43) v2(73.84,54.43) ; 56.67,28.25 55.94,28.97 55.94,30.1 54.25,31.79 v2(54.25,31.85) v2(54.25,34.19) v2(54.25,36.3) 54.25,36.45 v2(54.85,37.05) 55.04,37.24 v2(55.04,40.16) 55.04,40.87 v2(55.85,41.68) v2(56.69,42.52) ; v2(56.7,30.42) v2(54.99,32.13) 54.96,32.16 v2(54.96,34.22) v2(54.96,35.99) 54.96,36.1 55.75,36.88 v2(55.75,37.1) 55.75,40.54 v2(56.74,41.53) ; v2(61.42,54.55) v2(61.42,55.73) 61.42,60.17 62.2,60.95 62.2,61.95 62.4,62.15 v1(62.4,62.45) ; 71.65,39.07 71.65,25.55 v2(65.99,19.89) v2(64.59,19.89) v2(62.84,19.89) v2(61.14,19.89) v2(59.33,19.89) 58.62,19.89 v2(57.06,21.46) v2(56.28,22.23) v2(55.32,23.19) v2(55.32,24.41) v2(55.32,26.09) 55.32,26.14 56.03,26.85 56.03,27.59 v2(56.59,28.15) 56.67,28.22 ; 71.65,39.07 71.65,39.5 v2(71.37,39.78) v2(70.41,40.74) ; 71.65,39.07 70.41,40.31 v2(70.41,40.74) ; 66.57,53.18 66.77,53.38 v2(67.21,53.82) v2(68.47,55.08) v2(70.1,56.7) ; v2(58.01,56.09) v2(58.01,54.75) 58.01,54.01 v2(58,54) 58,53.89 59.46,52.43 v2(59.46,51.72) ; 56.77,40.07 v2(56.77,38) v2(56.77,36.68) 56.77,36.43 55.98,35.64 v2(55.98,34.66) v2(55.98,33.33) 55.98,32.87 56.5,32.35 v2(56.84,32.35) ; 64.64,31.67 64.64,30.84 v2(64.13,30.33) ; 64.64,31.67 64.64,35.45 63.84,36.25 63.22,36.25 v2(62.79,36.68) v2(62.23,37.24) 62.2,37.26 v2(62.2,38.81) ; 64.64,31.67 64.11,31.14 ; 67.59,27.51 v2(67.59,28.59) v2(67.59,30.53) v2(67.59,32.26) v2(67.59,34.14) v2(67.59,35.51) 67.59,37.01 v2(67.56,37.04) v2(66.24,38.36) ; v2(70.41,40.74) 70.41,41.94 69.85,42.5 68.86,43.49 ; v2(65.01,55.31) 64.54,54.84 v2(64.54,53.52) v2(64.54,52.03) ; 66.19,28.78 66.88,29.47 ; 66.19,28.78 v2(66.88,28.78) 66.88,29.47 ; 66.19,28.78 v2(65.99,28.58) ; 66.88,29.47 v2(66.88,30.51) v2(66.88,32.26) v2(66.88,34.11) v2(66.88,35.46) 66.88,36.68 v2(66.83,36.73) v2(65.48,38.08) ; v2(68.73,50.04) 69.8,50.04 70.21,50.45 v2(70.41,50.45) ; 66,39.66 65.8,39.87 ; 68.59,51.28 v2(68.27,51.28) ; 68.59,51.28 68.98,51.68 69.04,51.68 ; 68.59,51.28 v2(69.04,51.28) 69.04,51.68 ; 68.73,45.49 68.88,45.34 v2(69.42,45.34) v2(71.52,45.34) 73.21,45.34 v2(74,44.55) ; 69.04,51.68 69.04,52.36 v2(70.62,53.95) 70.62,53.93 72.24,53.93 v2(72.24,53.91) ; v2(72.36,44.63) v2(69.87,44.63) ; v2(76.58,42.8) 76.33,42.55 v2(75.6,42.55) ; v2(59.99,39.07) v2(59.99,37.19) ; v2(65.5,30.09) 65.66,30.24 v2(65.66,32.16) v2(65.66,34.06) v2(65.66,35.91) 65.66,35.92 v2(64.62,36.96) ; v2(58.27,35.99) 57.78,36.48 v2(57.78,36.71) v2(57.78,38.38) 57.78,39.76 v2(57.9,39.88) ; 58.01,60.96 v2(57.15,60.96) 56.91,60.96 56.4,60.45 56.4,59.9 57.16,59.14 v2(57.16,58.27) v2(57.16,56.09) 57.16,54.86 57.15,54.85 v2(57.15,54.75) 57.16,54.74 57.16,54.01 v2(57.15,54) 57.15,53.69 58.7,52.15 v2(58.7,51.67) ; v2(68.02,39.55) 69.77,37.8 v2(69.77,37.75) v2(69.77,35.69) v2(69.77,34.24) v2(69.77,32.51) v2(69.77,30.61) v2(69.77,28.86) v2(69.77,27.59) v2(69.77,26.39) 69.77,26.37 v2(68.68,25.28) v2(67.71,24.31) v2(66.9,23.5) v2(66.24,22.84) 65.2,21.8 v2(65.15,21.8) v2(63.51,21.8) v2(61.21,21.8) 59.71,21.8 v2(59.31,22.2) ; 60.11,29.14 59.43,29.14 59.43,29.62 v2(59.57,29.76) 60.61,30.79 v2(61.01,31.19) v2(61.01,32.67) 61.01,33.77 v2(61.02,33.78) ; v1(61.2,62.45) 61.2,61.1 60.6,60.5 v2(60.6,55.68) v2(60.6,54.55) ; v2(58.8,39.27) v2(58.8,38.2) v2(58.8,37.06) ; v2(62.86,51.62) v2(62.86,52.99) v2(62.86,54.74) v2(62.86,56.47) v2(62.86,58.3)
  TOP w0.5: 81.4,32.55 81.1,32.85 v1(81.1,34.2) v1(81.1,40.4) v1(81.1,44.85) ; v1(73.2,74.2) 73.15,74.25 67.65,74.25 v1(67.6,74.2) ; v1(79.75,29.05) 79.75,31.65 79.5,31.9 v1(79.5,34.2) v1(79.5,40.4) ; v1(80.3,40.4) v1(80.3,34.2) 80.3,32.35 80.75,31.9 v1(80.75,29.1) ; 84.35,41.1 84.3,41.15 v1(84.3,44.85) v1(84.3,46.1) 84.3,47.4 v1(84.35,47.45) 84.45,47.55 v1(84.45,51.2) v1(84.45,52.2) v1(84.45,53.2) 84.45,55.9 84,56.35 ; v1(78.8,26.4) v1(78.8,29.05) 78.8,31.4 78.7,31.5 v1(78.7,34.2) v1(78.7,40.4) 78.7,45.55 v1(79.3,46.15) ; v2(54.95,42.85) 51.25,42.85 50.2,41.8 50.2,35.9 48.2,33.9 ; v1(76.6,74.2) 76.65,74.25 82.95,74.25 v1(83,74.2) ; 36.25,74.25 50.9,74.25 ; v1(84.65,17.75) 84.1,17.75 83.75,17.4 81.9,17.4 80.5,18.8 78.1,18.8 v1(77.2,19.7) 74,22.9 v1(74,23.6) v1(74,26.4) v1(74,29.6) 74,36.95 73.03,37.92 73.03,39.98 71.65,41.35 71.65,43.1 UNK5C11.1 ; v1(84.65,15.65) 81.9,15.65 79.95,17.6 77.6,17.6 v1(76.72,18.48) 72.55,22.65 v2(72.55,24.9) ; v1(84.75,35.95) 84.75,37.35 85.7,38.3 85.7,47.3 v1(85.4,47.6) v1(85.4,49.2) v1(85.4,51.2) 85.4,56.65 84.75,57.3 v1(84.75,57.89)
  TOP w0.6: C30.2 16.5,3.65 ; C30.2 15.45,2.05 ; C30.2 C3.2 ; C3.2 15.45,9 ; C3.2 16.5,7.4
  TOP w1: C205.2 46.25,72.15 ; C205.2 48.95,72.15 ; C205.2 47.6,69.6 ; 80.95,72.15 C323.2 ; C323.2 78,72.15 ; C323.2 79.6,69.6 ; C223.2 39.15,72.15 ; C223.2 36.45,72.15 ; C223.2 37.8,69.6 ; C305.2 71.15,72.15 ; C305.2 68.45,72.15 ; C305.2 69.8,69.6
  MID1(L2) w0.3: 54.85,72.6 UNK2CON1.1 54.85,70.4
  MID2(L3) w0.3: 54.85,70.4 UNK2CON1.1 54.85,72.6
  BOTTOM w0.1: v1(80.25,13.95) 80.2,13.9 80.2,10.85 80.85,10.2 81.85,10.2 82.25,9.8 ; 31.09,60.99 v1(31.1,61) ; 64.58,26.95 64.58,26.95 UNK3R10.1 ; v1(86.95,24.3) 86.95,24.15 C253.1 ; v1(98,32.1) v1(99.95,32.1) ; v1(30.6,25.75) 30.59,25.76 C322.1 ; UNK4C2.1 57.65,45.24 ; v3(72.6,34.95) v3(72.6,33.3) v3(72.6,31.45) v2(72.6,29.6) v2(72.6,27.85) v2(72.6,26.2) 72.6,24.95 v2(72.55,24.9) v2(71.85,24.2) v2(70.7,23.05) v2(69.8,22.15) v2(68.9,21.25) v2(67.9,20.25) 67.54,19.89 66.34,19.89 ; 86.65,61.1 88,61.1
  BOTTOM w0.102: 66.21,42.33 66.21,42.35 ; 66.21,42.33 66.21,42.22 ; 66.21,42.33 66.39,42.51 66.52,42.64 66.53,42.64 ; 66.21,42.35 66.11,42.44 ; 66.21,42.35 66.21,42.64 ; v2(61.19,39.83) 61.18,39.84 61.18,40.63 61.34,40.78 61.34,41.66 61.07,41.93 61.07,42.19 ; 63.45,42.4 63.4,42.43 ; 63.45,42.4 63.7,42.38 63.73,42.41 ; 63.45,42.4 63.86,41.97 ; 63.45,42.4 62.52,42.4 ; 63.4,42.43 63.71,42.43 ; 63.4,42.43 63.32,42.52 63.32,42.62 ; 63.4,42.43 62.57,42.43 ; 64.65,42.62 64.63,42.64 ; 64.65,42.62 64.88,42.4 ; 64.65,42.62 v2(64.62,42.64) 64.63,42.64 ; 64.91,42.4 64.91,42.33 ; 64.91,42.4 64.91,42.42 ; 64.91,42.4 64.88,42.4 ; 64.91,42.33 64.93,42.31 ; 64.91,42.33 64.91,42.33 ; 64.91,42.33 64.91,42.3 ; 64.92,42.18 64.91,42.17 ; 64.92,42.18 64.91,42.2 ; 64.92,42.18 64.99,42.25 ; 64.91,42.17 64.91,41.62 65.02,41.51 65.02,41.1 v2(64.67,40.74) ; 64.91,42.17 64.91,42.2 ; 64.78,42.32 64.71,42.4 ; 64.78,42.32 64.26,42.32 64.26,42.35 64.21,42.4 ; 64.78,42.32 64.91,42.2 ; 64.71,42.4 64.62,42.49 64.62,42.62 64.84,42.4 ; 64.71,42.4 64.84,42.4 ; 64.71,42.4 64.21,42.4 ; 61.07,42.19 61.07,42.29 ; 61.07,42.19 60.89,42.38 ; 65.03,42.42 64.97,42.36 ; 65.03,42.42 65.24,42.62 ; 65.03,42.42 65.16,42.42 ; 65.03,42.42 64.96,42.42 ; 64.97,42.36 64.93,42.31 ; 64.97,42.36 64.96,42.37 64.96,42.42 ; 64.73,46.43 v2(64.62,46.55) ; 66.54,42.51 66.21,42.19 66.21,42.22 ; 66.54,42.51 66.57,42.64 ; 66.54,42.51 66.66,42.63 ; 62.3,42.62 62.35,42.57 ; 62.3,42.62 62.3,42.64 ; 62.3,42.62 62.3,42.35 ; 62.35,42.57 62.35,42.32 ; 62.35,42.57 62.35,42.64 ; 62.35,42.57 62.38,42.55 62.38,42.38 ; 64.93,42.31 64.99,42.25 ; 64.93,42.31 64.91,42.3 ; 64.08,26.34 v2(64.11,26.34) ; 64.08,26.34 63.23,26.34 ; 64.08,26.34 64.18,26.44 66.32,26.44 v2(66.42,26.34) ; 62.35,42.32 62.38,42.34 ; 62.35,42.32 62.35,42.14 ; 62.35,42.32 62.33,42.29 ; 60.77,42.59 60.78,42.61 ; 60.77,42.59 60.76,42.6 ; 60.77,42.59 60.76,42.59 60.73,42.59 ; 60.78,42.61 60.8,42.61 61.07,42.34 ; 60.78,42.61 v2(60.71,42.64) ; 60.78,42.61 60.81,42.63 v2(60.71,42.64) ; 63.23,26.34 63.23,25.92 62.79,25.48 61.05,25.48 60.6,25.92 60.59,25.9 ; 63.23,26.34 61.43,26.34 60.93,26.84 v2(60.41,26.84) 60.4,26.84 ; v2(60.71,42.64) 60.68,42.59 ; v2(60.71,42.64) 60.73,42.59 ; v2(60.71,42.64) 60.75,42.64 ; v2(60.71,42.64) 60.95,42.41 ; v2(60.71,42.64) 60.73,42.6 ; v2(60.71,42.64) 60.73,42.63 ; v2(61.36,42.64) 61.36,42.63 61.07,42.34 ; 60.5,42.41 60.49,42.42 ; 60.5,42.41 60.53,42.38 60.89,42.38 ; 60.5,42.41 60.86,42.41 ; 62.3,42.19 62.35,42.14 ; 62.3,42.19 62.3,42.27 ; 62.3,42.19 61.97,42.52 61.97,42.64 62.3,42.31 ; 62.35,42.14 62.35,41.77 62.13,41.54 62.13,41.52 62.11,41.51 62.11,41.42 62.11,41.42 v2(62.1,41.41) ; 64.91,42.42 64.91,42.64 ; 64.91,42.42 64.96,42.42 ; 61.07,42.34 61.07,42.63 ; 61.07,42.34 61.07,42.29 ; v2(66.88,28.78) 67.03,28.98 67.03,27.99 66.29,27.26 v2(65.66,27.26) ; 66.11,42.44 66.09,42.42 66.01,42.42 ; 66.11,42.44 65.93,42.62 65.93,42.63 v2(65.92,42.64) 65.81,42.63 ; 64.88,42.4 64.84,42.4 ; 64.88,42.4 64.91,42.37 64.91,42.33 ; 60.68,42.59 60.86,42.41 ; 60.68,42.59 60.67,42.6 ; 60.68,42.59 60.73,42.59 ; 62.42,42.38 62.38,42.38 ; 62.42,42.38 62.68,42.64 62.69,42.64 62.69,42.55 62.57,42.43 ; 62.42,42.38 62.52,42.4 ; 62.42,42.38 62.38,42.34 ; 62.38,42.38 62.38,42.34 ; 64.91,42.64 64.69,42.64 ; 64.91,42.64 64.94,42.64 ; 60.73,42.63 60.73,42.6 ; 60.73,42.63 60.76,42.6 ; 60.73,42.6 60.76,42.6 ; 60.73,42.6 60.73,42.59 ; 60.01,29.26 v2(60.01,29.24) ; 64.91,42.33 64.91,42.29 ; 64.91,42.33 64.84,42.4 ; 64.91,42.29 64.91,42.2 ; 64.91,42.29 64.91,42.3 ; v2(59.43,28.35) 59.44,28.31 59.32,28.19 59.32,27.94 ; 63.96,48.17 63.97,48.17 ; 60.89,42.38 60.86,42.41 ; 60.89,42.38 60.98,42.38 ; 60.86,42.41 60.95,42.41 ; 66.21,42.22 66.01,42.42 ; 65.81,42.63 65.94,42.51 65.94,42.49 66.01,42.42 ; 65.81,42.63 65.8,42.64 ; 65.81,42.63 65.81,42.64 ; 63.86,41.97 v2(63.97,41.99) 63.99,42.02 63.9,42.02 63.86,41.97 ; 63.86,41.97 63.28,41.39 63.28,41.33 63.28,41.33 v2(63.28,41.32) ; 65.16,42.42 64.99,42.25 ; 65.16,42.42 65.25,42.51 65.25,42.62 ; 65.16,42.42 66.01,42.42 ; 61.4,49.11 v2(61.36,49.15) 61.36,49.15 ; 59.32,27.94 58.19,27.94 v2(57.73,28.4) 57.22,28.91 57.22,29.09 56.87,29.44 56.87,30.62 56.96,30.72 UNK3C19.1 ; 59.32,27.94 59.32,27.42 59.9,26.84 60.4,26.84 ; 64.21,42.4 v2(63.97,42.64) 63.99,42.64 64.01,42.62 ; 62.3,42.31 62.3,42.27 ; 62.3,42.31 62.3,42.35 ; 62.3,42.31 62.33,42.29 ; 62.3,42.27 62.33,42.29 ; 66.57,42.64 66.56,42.63 ; 66.57,42.64 66.66,42.63 ; 66.57,42.64 66.53,42.64 ; 60.08,42.01 v2(60.06,41.99) 60.42,41.65 60.42,41.04 v2(60.06,40.69) ; 65.95,28.58 65.92,28.55 v2(65.99,28.58) 66,28.59 ; 61.07,42.29 60.95,42.41 ; 64.22,30.34 v2(64.13,30.33) ; 62.02,31.4 62.02,30.52 62.47,30.08 ; 66.56,42.63 66.53,42.63 66.53,42.64 ; 66.56,42.63 66.66,42.63 ; 60.78,35.99 60.74,36.03 60.74,36.13 59.99,36.88 v2(59.99,37.19) ; v2(64.62,45.24) 64.73,45.36 ; 60.4,26.84 60.54,27.07 62.01,27.07 62.13,26.95 64.58,26.95 ; 66.67,42.64 66.66,42.63 ; 64.69,42.64 64.63,42.64 ; 64.69,42.64 64.71,42.62 ; 64.94,42.64 64.96,42.62 64.96,42.42 ; 64.94,42.64 65.27,42.64 ; v2(70.71,43.66) 70.71,43.72 69.87,44.55 v2(69.87,44.63) 69.52,44.99 68.81,44.99 UNK5C10.1 ; 66.53,42.64 66.52,42.64 ; 62.52,42.4 62.57,42.43 ; 62.3,42.35 v2(62.01,42.64) ; 58.76,41.35 58.76,41.35 v2(58.76,41.35) ; v2(62.45,29.14) 62.47,29.16 62.47,29.12 ; v2(61.36,43.94) 60.98,43.56 60.98,42.64 ; v2(63.7,39.88) 63.73,39.42 64.35,38.8 64.95,38.8 65.48,38.27 v2(65.48,38.08)
  BOTTOM w0.127: v2(60.01,29.24) 60.13,29.2 60.03,29.1 60.01,29.1 60.01,27.77 60.3,27.49 61.5,27.49 62.13,28.11 65.71,28.11 65.98,28.38 65.98,28.57 ; v2(66.3,51.36) 66.08,51.59 66.08,52.95 66.42,53.29 v2(66.7,53.29) ; 68.45,51.46 v2(68.27,51.28)
  BOTTOM w0.15: 83.35,48.15 83.1,47.9 78,47.9 77.65,47.55 77.55,47.55 ; 50.75,52.5 49.3,53.95 47.35,53.95 46.1,55.2 37.5,55.2 35.13,52.83 ; 51.6,54.36 51.6,53.4 53.75,51.25 v2(54.35,51.25) ; 35.9,54.4 37.2,55.7 46.41,55.7 47.66,54.45 49.85,54.45 53.75,50.55 v2(54.35,50.55) ; 79.12,22.98 80.72,22.98 ; 53.55,49.75 53.55,49.85 53.5,49.85 53.5,50.1 51.9,51.7 50.75,51.7
  BOTTOM w0.152: 63.85,48.06 63.19,48.72 62.66,48.72
  BOTTOM w0.2: v1(77.95,15.8) 77.95,15.4 77.45,14.9 77.45,13.2 77.65,13 77.65,10.1 78.8,8.95 80.9,8.95 81.18,8.67 J813.13 81.18,7.12 ; C332.1 33.31,54.86 33.85,55.4 36.1,55.4 36.9,56.2 46.61,56.2 47.86,54.95 51.01,54.95 51.6,54.36 v1(52.12,54.36) 52.63,53.85 53.25,53.85 53.4,54 ; 54.55,58.35 57.08,58.35 v2(57.16,58.27) ; v1(27.45,37.08) 27.43,37.06 R301.2 ; C317.1 31.09,27.79 v1(30.55,27.25) ; v1(85.95,35.95) 85.96,35.94 C241.1 ; 86.18,7.17 J813.3 86.18,8.72 84.65,10.25 84.35,10.25 83.75,10.85 83.75,12.95 83.05,13.65 83.05,15.1 ; R223.1 89.62,38.08 v1(89.6,38.1) ; v1(32.3,27.25) 32.31,27.26 C350.1 ; 80.18,7.23 J813.15 79.25,8.1 ; 81.18,2.42 83.68,2.42 ; 81.18,2.42 81.18,3.83 ; 81.18,2.42 80.53,2.42 ; 81.18,2.42 81.18,1.37 ; 83.68,2.42 83.68,3.73 ; 83.68,2.42 86.18,2.42 ; 83.68,2.42 83.68,1.27 ; 86.18,2.42 86.18,3.68 ; 86.18,2.42 86.88,2.42 ; 86.18,2.42 86.18,1.22 ; U302.9 30.31,51.29 v1(30.35,51.25) ; v1(80.75,22.15) 81.95,22.15 82,22.1 82,21.15 81.55,20.7 81,20.7 ; 81,20.7 79.45,19.15 79.45,15.7 79.6,15.55 v1(79.6,12.9) ; 81,20.7 81,21.15 80.78,21.38 80.28,21.38 78.85,19.95 78.85,13.95 v1(78.9,13.9) ; C342.2 35.13,52.83 ; v1(86.8,38.15) 87.1,38.15 87.2,38.05 C246.1 ; v1(84.75,35.95) 84.74,35.94 C254.1 ; 82.25,9.8 83.18,8.87 J813.9 83.18,7.27 ; 83,15.1 83.75,15.85 UNK5D11.2 ; v1(86.7,33.9) 86.74,33.86 U202.9 ; v1(44.25,30.35) 44.45,30.15 UNK4C49.1 45.35,29.7 ; v1(80.25,13.95) 80.25,15.75 79.95,16.05 79.95,18.45 81.5,20 82.5,20 v1(82.5,20.85) ; 39.2,5.5 38.3,5.5 v1(38,5.2) ; C217.1 v1(86.85,57.14) ; v1(84.75,57.89) 84.74,57.88 C252.1 ; v1(33.65,54) 34.05,54.4 35.9,54.4 ; U201.9 v1(86.85,55.8) ; v1(89.6,48.06) 89.62,48.08 R201.2 ; 50.75,52.5 50.75,51.7 ; C204.1 v1(89,46.1) ; 78.5,48.7 81.15,48.7
  BOTTOM w0.203: 63.55,44.5 63.55,42.64 v2(63.32,42.64) ; 62.47,30.08 63.65,30.08 63.9,30.34 v2(64.13,30.33) ; v2(64.54,53.52) 64.59,53.52 64.67,53.44 64.67,52.19 64.54,52.06 v2(64.54,52.03) ; 64.6,42.62 v2(64.62,42.64) ; v2(65.01,55.31) 65.23,55.09 65.23,51.56 v2(65.06,51.4)
  BOTTOM w0.25: C222.1 87.2,59.8 87,60 ; v1(31.9,5.1) v1(31.9,5.9)
  BOTTOM w0.254: C102.1 63.1,51.07 63.1,49.62 62.66,49.18 v2(62.66,49.15) v2(62.66,48.5) ; 61.4,49.11 61.36,49.14 61.36,49.15 ; 62.53,29.09 64.46,29.09 64.82,29.44 64.82,30.34 ; 62.53,29.09 62.02,29.09 61.51,29.59 60.01,29.59 60.01,29.26 ; 62.53,29.09 v2(62.45,29.14) ; 56.45,48.7 v2(55.37,49.79) ; 60.08,42.01 60.49,42.42 v2(60.71,42.64) ; 72.64,46.89 72.36,47.17 70.79,47.17 UNK2C17.2 ; 61.35,42.63 v2(61.36,42.64)
  BOTTOM w0.3: C249.2 46.8,72.1 ; C249.2 47.35,71.4 ; C249.2 46.8,70.7 ; U302.9 28.37,51.29 v1(26.62,53.04) ; 13.35,47.95 C360.2 12.65,47.4 ; v1(88.38,32.11) v1(89.38,32.11) v1(90.43,32.11) ; 84.19,35.2 C254.1 ; 39.25,63.6 UNK2T17.1 ; UNK2T17.1 40.75,63.6 ; UNK2T17.1 40,62.85 ; v2(64.54,53.52) 64.54,54.81 64.35,55 64.35,55.65 64.65,55.95 64.65,57.65 65.04,58.04 70.66,58.04 73.84,54.87 v2(73.84,54.43) ; C25.1 13.85,18.6 ; C25.1 13.85,17.5 ; C25.1 14.35,18.05 ; R342.2 12.65,45.45 ; R342.2 13.2,44.75 ; R342.2 12.65,44.05 ; UNK4C8.1 43.35,51.4 ; UNK4C8.1 42.8,50.9 ; UNK4C8.1 42.25,51.4 ; 111.5,51.5 R234.2 ; R234.2 111.5,52.9 ; R234.2 112.05,52.2 ; 98.75,0.95 J814.8 ; J814.8 97.6,2.15 ; J814.8 98.75,3.35 ; 63.14,45.32 UNK2C16.1 ; UNK2C16.1 62.64,45.82 ; UNK2C16.1 63.14,46.32 ; v1(94.15,55.8) U201.22 92.18,55.8 91.18,54.8 ; C103.1 78.2,44.15 ; C103.1 77.65,43.65 ; C103.1 77.1,44.15 ; UNK4R9.2 38.8,42.3 ; UNK4R9.2 39.35,41.8 ; UNK4R9.2 38.25,41.8 ; 93.65,3.9 J814.5 ; J814.5 93.2,4.83 ; J814.5 93.65,5.75 ; C342.2 32.6,53.53 ; 63.02,36.02 UNK3C20.1 ; UNK3C20.1 63.53,35.52 ; UNK3C20.1 64.03,36.02 ; 76,46.3 C105.1 76.55,46.8 ; C264.2 98.7,48.1 ; C264.2 98.15,47.4 ; C264.2 98.7,46.7 ; 29.26,37.4 C301.2 v1(30.85,36.85) ; 31.95,54.31 C332.1 31.95,55.41 ; 70.82,50.6 UNK2R15.1 ; UNK2R15.1 70.31,51.1 ; UNK2R15.1 70.82,51.6 ; UNK2R15.1 71.32,51.1 ; 93.5,26.72 C231.2 ; C231.2 93.5,28.12 ; C231.2 94.05,27.42 ; 90.68,32.36 U202.25 98.04,32.36 C238.2 ; 90.68,32.36 v1(90.43,32.11) ; 90.68,32.36 91.18,32.86 ; 98.59,55.07 C214.2 98.04,55.77 ; T312.1 55.3,68.6 ; T312.1 56.05,67.85 ; T312.1 54.55,67.85 ; 99.67,27.14 C229.1 ; C229.1 99.67,28.54 ; C229.1 100.22,27.84 ; 99.95,54.06 99.93,54.04 98.05,54.04 ; 99.95,54.06 v1(99.99,54.1) 99.95,54.14 99.95,55.06 98.04,55.06 98.04,54.3 U201.25 90.68,54.3 ; 99.95,54.06 v1(98.05,54.06) ; UNK4C47.2 44.4,38.9 ; UNK4C47.2 43.7,38.35 ; UNK4C47.2 45.1,38.35 ; R341.1 7.85,59.65 ; R341.1 8.55,59.1 ; R341.1 7.15,59.1 ; 56.99,31.85 UNK3C11.1 ; UNK3C11.1 57.49,31.35 ; UNK3C11.1 58,31.85 ; UNK3C11.1 57.49,32.35 ; U201.39 88.68,52.3 ; 88.68,52.3 89.18,52.8 ; 88.68,52.3 88.18,51.8 U201.1 ; 56.44,34.81 UNK3C9.1 ; UNK3C9.1 56.44,35.81 ; UNK3C9.1 55.94,35.31 ; UNK3C9.1 56.95,35.31 ; T318.1 40.3,68.6 ; T318.1 39.55,67.85 ; T318.1 41.05,67.85 ; T318.1 40.3,67.1 ; 59.06,35.31 UNK3C10.1 ; UNK3C10.1 59.57,34.81 ; UNK3C10.1 59.57,35.81 ; C268.2 98.7,24.7 ; C268.2 98.15,24 ; C268.2 98.7,23.3 ; 38.6,12.9 Q3.2 ; Q3.2 39.2,12.3 ; Q3.2 39.8,12.9 ; Q3.2 39.2,13.5 ; 89.18,30.86 U202.3 86.93,30.86 ; 89.18,30.86 88.18,29.86 U202.1 ; 89.18,30.86 89.68,31.36 ; 61.48,44.78 UNK3C5.1 ; UNK3C5.1 62.48,44.78 ; UNK3C5.1 61.98,45.28 ; UNK3C5.1 61.98,44.27 ; 83.9,32.31 C242.2 ; C242.2 84.45,31.61 ; C242.2 84.45,33.01 ; 90.18,31.86 v1(90.43,32.11) ; 90.18,31.86 89.68,31.36 ; 90.18,31.86 U202.5 86.93,31.86 ; v1(90.43,32.11) 88.68,33.86 U202.9 ; v1(90.43,32.11) 90.68,31.86 ; 55.47,24.44 UNK3C35.1 ; UNK3C35.1 55.97,24.94 ; UNK3C35.1 56.47,24.44 ; UNK3C35.1 55.97,23.93 ; 101.5,28.05 R220.1 ; R220.1 100.95,28.75 ; R220.1 C233.2 ; UNK3C42.1 62.8,33.96 ; UNK3C42.1 61.79,33.96 ; UNK3C42.1 62.29,33.46 ; C241.1 86.51,35.2 ; T308.1 66.05,67.85 ; C362.2 18.95,37.6 ; C362.2 18.4,36.9 ; C362.2 18.4,38.3 ; U301.17 25.87,28.97 ; C216.1 R205.2 ; C216.1 102.2,57.4 ; C216.1 102.9,57.95 ; R205.2 105,57.4 ; R205.2 104.3,57.95 ; C340.1 R321.2 ; C340.1 16.05,51.1 ; C340.1 15.5,51.8 ; R321.2 16.05,49.7 ; R321.2 15.5,49 ; 98.15,38.6 R236.2 ; R236.2 98.7,37.9 ; R236.2 98.7,39.3 ; 37.15,31.25 C22.2 ; C22.2 38.55,31.25 ; C22.2 37.85,31.8 ; UNK3C8.2 60.78,32.51 ; UNK3C8.2 60.1,31.85 ; UNK3C8.2 60.78,31.2 ; 56.66,34.2 UNK3C21.1 ; UNK3C21.1 57.16,33.69 ; UNK3C21.1 57.16,34.7 ; UNK3C21.1 57.66,34.2 ; UNK3C38.1 62.79,32.85 ; UNK3C38.1 62.28,32.35 ; UNK3C38.1 62.28,33.35 ; UNK3C38.1 61.78,32.85 ; 94.1,44.5 C203.1 ; C218.2 84.45,54.95 ; C218.2 83.9,54.25 ; C218.2 84.45,53.55 ; v1(90.43,54.05) 88.68,55.8 U201.9 ; v1(90.43,54.05) 90.68,54.3 ; v1(90.43,54.05) 90.68,53.8 ; v1(90.43,54.05) 90.18,53.8 ; v1(90.43,54.05) v1(89.43,54.05) v1(88.38,54.05) ; v1(19,31.1) v1(17.1,31.1) 17.1,30.08 19.01,30.08 19.01,30.84 U301.25 26.37,30.84 v1(26.62,31.09) ; 27.37,31.84 U301.4 30.12,31.84 ; 27.37,31.84 27.87,32.34 ; 27.37,31.84 26.87,31.34 ; 18.4,38.6 R339.1 ; R339.1 18.95,39.3 ; R339.1 18.4,40 ; 26.87,53.29 27.37,53.79 ; 26.87,53.29 v1(26.62,53.04) ; 26.87,53.29 U302.5 30.12,53.29 ; 27.37,53.79 27.87,54.29 ; 27.37,53.79 U302.4 30.12,53.79 ; 87.53,29.42 U202.1 ; U202.1 86.93,29.86 ; 62.1,45.85 UNK2C20.1 61.6,45.35 ; 89.68,31.36 U202.4 86.93,31.36 ; 90.18,53.8 89.68,53.3 ; 90.18,53.8 U201.5 86.93,53.8 ; 89.68,53.3 U201.4 86.93,53.3 ; 89.68,53.3 89.18,52.8 ; 55.49,30.7 UNK3C27.1 ; UNK3C27.1 56.49,30.7 ; UNK3C27.1 55.99,30.19 ; UNK3C27.1 55.99,31.2 ; 90.68,31.86 U202.26 98.04,31.86 ; 90.68,31.86 91.18,31.36 ; 27.5,61.7 v1(27.43,61.7) C326.1 27.98,60.99 ; 10.4,56.35 C359.1 ; C359.1 11.1,56.9 ; C359.1 11.8,56.35 ; 57.38,30.21 UNK3C19.1 ; UNK3C19.1 57.88,30.72 ; UNK3C19.1 57.38,31.22 ; C77.2 46.6,33.2 ; C77.2 45.9,32.65 ; C77.2 45.2,33.2 ; 90.17,46.1 C204.1 89.62,45.6 ; v1(32.25,49.21) 32.31,49.27 C352.1 32.86,49.94 ; 33.15,30.89 C318.2 32.6,31.59 ; C56.2 45.81,18.41 ; C56.2 45.16,17.46 ; C56.2 44.51,18.41 ; C56.2 45.16,19.36 ; C51.2 47.45,12.5 ; C51.2 45.55,12.5 ; C51.2 46.5,11.85 ; C51.2 46.5,13.15 ; C21.2 38.1,33.65 ; C21.2 37.55,34.35 ; C21.2 37.55,32.95 ; 78.93,1.82 J813.S1 ; J813.S1 78.93,3.88 ; J813.S1 79.38,2.85 ; J813.S1 78.48,2.85 ; 17.1,53.03 17.1,52.03 19.01,52.03 19.01,52.79 U302.25 26.37,52.79 ; 17.1,53.03 19,53.03 ; 17.1,53.03 v1(17.1,53.05) v1(19,53.05) ; 29.3,47.71 C346.1 ; C346.1 29.85,47.21 ; C346.1 30.4,47.71 ; 87.75,37.43 C246.1 86.65,37.43 ; 49.35,33.9 U55.2 ; 58.02,30.5 UNK3C26.2 ; UNK3C26.2 58.7,31.16 ; UNK3C26.2 59.38,30.5 ; 56.02,32.25 UNK3C2.1 ; UNK3C2.1 56.52,32.76 ; UNK3C2.1 55.52,32.76 ; UNK3C2.1 56.02,33.26 ; 77.6,32.95 C78.2 78.3,33.5 ; 30.12,32.34 U301.3 27.87,32.34 ; UNK3R6.1 63.59,44.5 ; UNK3R6.1 63.09,43.99 ; UNK3R6.1 62.59,44.5 ; UNK3R6.1 63.09,45 ; Q5.2 73.95,28.45 ; Q5.2 73.35,27.85 ; Q5.2 74.55,27.85 ; Q5.2 73.95,27.25 ; 96.75,4.7 J814.6 ; J814.6 98.05,3.65 ; J814.6 98.05,5.75 ; 91.26,53.22 92.18,52.3 U201.29 v1(94.15,52.3) ; 91.26,53.22 90.68,53.8 ; 91.26,53.22 91.18,53.14 U201.34 ; 71.71,44.05 UNK5R64.2 ; UNK5R64.2 72.21,44.55 ; UNK5R64.2 71.71,45.05 ; UNK5R64.2 71.2,44.55 ; 57.15,45.21 UNK4C2.1 58.15,45.21 ; 90.68,53.8 U201.26 98.04,53.8 C211.2 ; 99.67,35.67 C243.1 ; C243.1 100.22,36.37 ; C243.1 99.67,37.07 ; 51.85,10.8 U51.2 53.35,10.8 ; C308.1 32.45,32.92 ; C308.1 31.95,33.47 ; C308.1 31.95,32.37 ; T315.1 47.8,68.6 ; T315.1 47.05,67.85 ; T315.1 48.55,67.85 ; UNK2T25.1 48.7,63.6 v1(49,63.3) ; C233.2 101.5,30.85 ; C233.2 100.95,30.15 ; 22.95,26.4 C324.2 23.5,27.1 ; 26.37,53.29 U302.26 19.01,53.29 C335.2 ; 26.37,53.29 25.87,53.79 ; 26.37,53.29 v1(26.62,53.04) ; 91.18,54.8 U201.17 ; 91.18,54.8 90.68,54.3 ; v1(26.62,53.04) v1(27.62,53.04) v1(28.67,53.04) ; v1(26.62,53.04) 26.37,52.79 ; 43.15,38.35 UNK4C35.1 42.6,37.85 ; C343.1 17.38,49.47 ; C343.1 17.38,48.07 ; C343.1 16.83,48.77 ; UNK3C4.1 65.56,43.81 ; UNK3C4.1 65.05,43.31 ; UNK3C4.1 66.06,43.31 ; UNK3C4.1 65.56,42.81 ; 19.01,51.32 C338.2 18.46,52.02 ; 23.5,35.08 C306.2 22.95,35.78 ; 16.05,26.3 C358.2 15.5,27 ; R304.1 16.05,34.45 ; R304.1 15.5,35.15 ; R304.1 C309.2 ; 98.15,25.6 R235.1 ; R235.1 98.7,24.9 ; R235.1 98.7,26.3 ; 54.72,48.64 UNK2C4.2 ; UNK2C4.2 55.4,49.3 ; UNK2C4.2 56.08,48.64 ; 52.05,67.85 T313.1 ; T313.1 53.55,67.85 ; T313.1 52.8,68.6 ; C357.1 15.5,36.6 ; C357.1 16.05,35.9 ; C357.1 15.5,35.2 ; 26.37,31.34 v1(26.62,31.09) ; 26.37,31.34 25.87,31.84 ; 26.37,31.34 U301.26 19.01,31.34 C311.2 ; v1(26.62,31.09) 28.37,29.34 U301.9 30.31,29.34 v1(30.35,29.3) ; v1(26.62,31.09) 26.87,31.34 ; v1(26.62,31.09) v1(27.62,31.09) v1(28.67,31.09) ; 30.12,31.34 U301.5 26.87,31.34 ; 23.5,49.1 C348.2 22.95,48.4 ; U302.1 28.87,55.29 28.37,54.79 ; U302.1 30.12,55.29 ; U302.1 29.52,55.73 ; UNK5C13.1 97.65,7 ; UNK5C13.1 97.15,6.45 ; UNK5C13.1 97.15,7.55 ; 100.95,49 C259.1 101.5,49.7 ; 27.87,54.29 U302.3 30.12,54.29 ; 27.87,54.29 28.37,54.79 ; C79.2 52.55,35.55 ; C79.2 52.55,34.15 ; C79.2 53.1,34.85 ; 89.07,59.38 R207.1 89.62,59.4 88.9,59.4 v1(88.55,59.75) ; 40.5,41.95 UNK4C26.1 39.4,41.95 ; 25.87,31.84 U301.34 ; 25.87,31.84 24.87,32.84 U301.29 v1(22.85,32.84) ; 100.95,37.05 C262.2 ; C262.2 101.5,36.35 ; C262.2 101.5,37.75 ; 89.18,52.8 U201.3 86.93,52.8 ; C316.1 16.05,29.15 ; C316.1 15.5,29.85 ; C316.1 R305.2 ; 60.09,25.9 UNK3C40.1 ; C333.2 14.1,56.9 ; C333.2 R319.1 ; C333.2 14.8,56.35 ; 98.7,39.5 C269.1 ; C269.1 98.15,40.2 ; C269.1 98.7,40.9 ; 98.04,31.86 98.04,32.06 v1(98,32.1) ; 98.04,31.86 C235.2 ; 100.95,35.45 R221.2 ; R221.2 C240.1 ; R221.2 101.5,36.15 ; Q4.2 79.55,28.45 ; Q4.2 80.15,27.85 ; Q4.2 78.95,27.85 ; v1(79.5,22.35) 79.5,21.6 78.3,20.4 78.3,16.15 v1(77.95,15.8) ; R233.1 98.7,46.5 ; R233.1 98.15,45.8 ; R233.1 98.7,45.1 ; C311.2 19.01,32.81 ; C311.2 18.46,32.11 ; 14.55,18.1 R3.1 ; R3.1 15.05,18.65 ; R3.1 15.05,17.55 ; 62.08,29.62 UNK3C45.1 ; UNK3C45.1 62.58,30.12 ; UNK3C45.1 62.58,29.12 ; UNK3C45.1 63.09,29.62 ; 74.35,38.3 C76.2 ; C76.2 73.8,39 ; C76.2 74.35,39.7 ; UNK3R20.1 54.89,31.2 ; UNK3R20.1 54.39,30.7 ; UNK3R20.1 54.89,30.19 ; 28.37,54.79 U302.39 ; 69.1,42.92 C101.1 69.6,42.42 ; UNK2T28.1 v1(50.85,61.6) ; J814.10 93.8,3.35 ; J814.10 93.8,0.95 ; J814.10 92.65,2.15 ; J814.10 J814.9 ; 27.87,32.34 28.37,32.84 ; 85.55,16.05 UNK5D12.2 ; UNK5D12.2 86.05,16.7 ; UNK5D12.2 85.55,17.35 ; C217.1 85.96,57.64 ; T311.1 58.55,67.85 ; T311.1 57.05,67.85 ; T311.1 57.8,68.6 ; 17.38,34.66 C307.1 ; C307.1 17.38,36.06 ; C307.1 16.83,35.36 ; C367.1 13.2,46.4 ; C367.1 12.65,45.7 ; C367.1 12.65,47.1 ; C309.2 16.05,33.05 ; C309.2 15.5,32.35 ; C265.1 112.05,53.8 ; C265.1 111.5,53.1 ; C265.1 111.5,54.5 ; C52.1 48,12.2 ; C52.1 48.55,11.7 ; C52.1 47.45,11.7 ; 18.1,22.6 R340.2 ; R340.2 18.65,23.3 ; R340.2 18.1,24 ; C248.2 94.05,36.8 ; C248.2 93.5,37.5 ; C248.2 93.5,36.1 ; 55.97,26.01 UNK3C18.1 ; UNK3C18.1 55.47,26.52 ; UNK3C18.1 56.47,26.52 ; 28.37,32.84 28.87,33.34 U301.1 ; 28.37,32.84 U301.39 ; C235.2 98.59,31.09 ; C235.2 98.04,30.39 ; 57.65,25.54 UNK3C6.2 ; UNK3C6.2 58.33,26.19 ; UNK3C6.2 56.97,26.19 ; 86.93,51.8 U201.1 ; U201.1 87.53,51.36 ; 29.3,25.76 C322.1 29.85,25.26 ; U301.1 29.52,33.78 ; U301.1 30.12,33.34 ; 25.87,53.79 24.87,54.79 U302.29 v1(22.91,54.79) ; 25.87,53.79 U302.34 ; C260.2 109.25,55.4 ; C260.2 108.7,54.7 ; C260.2 108.7,56.1 ; U202.34 91.18,31.36 ; 91.18,31.36 92.18,30.36 U202.29 v1(94.15,30.36) ; 91.15,0.95 J814.11 ; J814.11 91.15,3.35 ; J814.11 90,2.15 ; J814.11 92.3,2.15 ; 79.35,62.45 80.3,61.5 84.95,61.5 85.4,61.05 85.4,60.15 85.15,59.9 84.25,59.9 v1(84.25,60.8) 84.15,60.9 79.7,60.9 79.22,61.38 ; 17.38,56.6 C329.1 ; C329.1 17.38,58 ; C329.1 16.83,57.3 ; C319.1 17.38,27.52 ; C319.1 16.83,26.82 ; C319.1 17.38,26.12 ; C245.1 94.15,41.7 ; 38.95,9.1 Q2.2 ; Q2.2 38.95,10.3 ; Q2.2 38.35,9.7 ; Q2.2 39.55,9.7 ; UNK2C11.1 56.91,44.83 ; UNK2C11.1 56.41,45.34 ; UNK2C11.1 55.91,44.83 ; 30.54,28 C317.1 ; 18.46,30.07 C314.2 19.01,29.37 ; C240.1 101.5,33.35 ; C240.1 100.95,34.05 ; 101.5,50.05 R204.1 ; R204.1 C209.2 ; R204.1 100.95,50.75 ; 48.65,7.65 C65.1 48.1,7.15 ; J814.7 91.85,5.75 ; J814.7 91.85,3.65 ; J814.7 93.15,4.7 ; J814.7 90.55,4.7 ; 100.95,27.15 C261.1 101.5,27.85 ; 58.07,43.01 UNK3C62.1 58.79,43.01 ; 55.11,41.31 UNK3C28.2 ; UNK3C28.2 55.09,40.37 ; UNK3C28.2 56.05,41.33 ; 54.4,43.99 UNK2C13.2 55.08,44.64 ; 49.55,67.85 T314.1 ; T314.1 50.3,68.6 ; T314.1 51.05,67.85 ; 44.65,41.55 UNK4C17.1 45.15,42.1 ; 22.95,43.5 C345.1 ; 84.61,52.22 C208.1 ; C208.1 85.11,52.77 ; C208.1 85.11,51.67 ; 84.19,57.14 C252.1 ; UNK2C22.1 59.31,51.13 ; UNK2C22.1 58.8,51.63 ; UNK2C22.1 58.3,51.13 ; 88.85,24.15 v1(89,24.15) C226.1 89.62,23.65 ; 93.5,48.72 C206.2 ; C206.2 94.05,49.42 ; C206.2 93.5,50.12 ; 57.14,42.21 UNK3C31.1 57.86,42.93 ; 39.15,50.4 UNK4C48.1 38.6,50.9 ; 15.5,27.05 R305.2 ; R305.2 16.05,27.75 ; UNK3C39.1 61.03,44.38 ; UNK3C39.1 60.03,44.38 ; UNK3C39.1 60.53,43.87 ; 88.43,1.82 J813.S5 ; J813.S5 87.98,2.85 ; J813.S5 88.43,3.88 ; J813.S5 88.88,2.85 ; UNK2C17.2 71.22,47.42 ; C211.2 98.59,53.04 ; C211.2 98.04,52.34 ; R319.1 12,56.35 ; R319.1 12.7,56.9 ; 83.75,17.35 UNK5D11.2 83.25,16.7 ; 54.85,70.4 UNK2CON1.1 54.85,72.6 ; C335.2 19.01,54.75 ; C335.2 18.46,54.05 ; C350.1 32.86,28 ; UNK3C46.1 57.68,22.05 ; UNK3C46.1 57.17,21.55 ; UNK3C46.1 57.17,22.55 ; UNK3C46.1 56.67,22.05 ; 69.33,63.5 T321.1 68.58,64.25 ; C207.1 99.67,50.48 ; C207.1 100.22,49.78 ; C207.1 99.67,49.08 ; C221.1 87.3,62.5 ; C221.1 87.3,61.1 ; C221.1 86.75,61.8 ; 75.7,49.65 C106.1 ; C106.1 76.8,49.65 ; C106.1 76.25,50.15 ; 100.95,52.15 C209.2 ; C209.2 101.5,52.85 ; v2(62.79,36.68) 63.4,36.07 ; v1(86.85,48.29) C201.2 87.79,47.74 ; 45.6,53.5 UNK4R7.1 45.1,52.95 ; C363.1 18.1,25.5 ; C363.1 18.1,24.1 ; C363.1 18.65,24.8 ; 94.05,22.55 C228.1 ; 26.37,52.79 25.87,52.29 U302.17 ; C219.1 99.67,59.02 ; C219.1 99.67,57.62 ; C219.1 100.22,58.32 ; 93.5,58.1 C224.2 ; C224.2 93.5,59.5 ; C224.2 94.05,58.8 ; 20.25,18.1 C12.1 19.75,18.65 ; J814.9 96.1,3.35 ; J814.9 96.1,0.95 ; J814.9 97.25,2.15 ; 87.79,25.79 C230.2 86.86,26.34 v1(86.85,26.35) ; UNK4C9.1 48.55,31.1 ; UNK4C9.1 48.05,31.65 ; UNK4C9.1 48.05,30.55 ; 8.75,59.1 C366.2 ; C366.2 9.45,59.65 ; C366.2 10.15,59.1 ; T320.1 69.33,60.96 ; T320.1 68.58,61.71 ; T320.1 68.58,60.21 ; T320.1 67.83,60.96 ; 48.8,5.45 C66.1 49.35,4.95 ; v1(94.15,33.86) U202.22 92.18,33.86 91.18,32.86 ; v1(22.94,51.29) U302.22 24.27,51.29 v1(24.57,51.59) ; U202.17 91.18,32.86 ; 29.26,59.35 C330.2 v1(30.3,58.8) ; v1(22.85,29.34) U301.22 24.27,29.34 v1(24.57,29.64) ; 27.98,39.04 C304.1 27.43,39.72 v1(27.35,39.8) ; 63.86,34.85 UNK3C58.1 ; R22.1 10.55,16.45 ; R22.1 9.45,16.45 ; R22.1 10,15.95 ; UNK4C18.1 46.1,40.9 ; UNK4C18.1 46.1,39.8 ; UNK4C18.1 46.6,40.35 ; 22.95,21.55 C321.1 ; v1(30.65,39.65) 30.65,39.04 C349.1 ; UNK2C6.2 54.38,48.64 ; UNK2C6.2 53.02,48.64 ; UNK2C6.2 53.7,49.3 ; 99.95,33.12 C238.2 ; C238.2 98.04,33.82 ; 23.5,57.08 C331.2 22.95,57.78 ; U202.39 88.68,29.81 ; 45.16,19.39 C54.2 ; C54.2 44.51,20.34 ; C54.2 45.16,21.29 ; C54.2 45.81,20.34 ; U54.2 74.8,35.55 ; 48.75,7.35 R59.1 ; 84.61,30.28 C232.1 ; C232.1 85.11,30.83 ; C232.1 85.11,29.73 ; v1(30.75,49.15) 31.09,49.49 C341.1 30.54,49.94 ; C351.1 31.09,60.99 ; C328.1 23,62.55 ; C303.1 23,40.6 ; 65.33,43.92 UNK5C9.1 ; UNK5C9.1 64.83,44.42 ; UNK5C9.1 65.83,44.42 ; UNK5C9.1 65.33,44.93 ; C250.1 46.75,70.1 ; C250.1 46.25,69.55 ; C250.1 46.25,70.65 ; C55.1 45.82,17.43 ; C55.1 45.82,16.33 ; C55.1 45.32,16.88 ; 86.65,59.38 C222.1 ; UNK4C34.1 45.15,43.2 ; UNK2C10.1 66.04,47
  BOTTOM w0.305: v2(63.52,35.54) 63.52,35.17 62.3,33.95 62.3,33.96 62.29,33.96 ; C251.1 80.9,46.1 80.13,46.87 v2(76.58,46.87) ; 64.73,44.43 64.73,46.43 ; UNK3C1.1 67.49,46.56 65.76,46.56 UNK2C10.1
  BOTTOM w0.381: 69.06,42.19 v2(69.06,41.48) ; 69.06,42.19 69.06,42.27 68.68,42.64 67.69,42.64 ; 69.06,42.19 68.72,42.53 68.66,42.53 68.65,42.54 67.62,42.54 ; 67.22,42.14 v2(67.22,41.99) ; 67.22,42.14 67.22,42.19 ; 67.22,42.14 67.62,42.54 ; 63.32,42.62 63.52,42.62 ; 63.32,42.62 v2(63.32,42.64) ; 63.32,42.62 63.01,42.62 62.99,42.64 ; 63.52,42.62 63.97,42.17 64,42.17 ; 63.52,42.62 63.99,42.62 ; 65.24,42.62 65.27,42.64 ; 65.24,42.62 64.71,42.62 ; 65.24,42.62 65.27,42.62 65.27,42.64 ; 65.27,42.64 v2(65.92,42.64) 66.76,42.64 ; 67.22,42.19 v2(67.22,42.64) ; 67.22,42.19 66.76,42.64 ; v2(67.22,42.64) 66.76,42.64 ; v2(67.22,42.64) 67.69,42.64 ; 66.21,42.51 66.89,42.51 ; 67.69,42.64 67.69,42.61 67.62,42.54 ; 64.71,42.62 64.62,42.62 ; 64.71,42.62 64.64,42.64 ; 63.99,42.62 64.45,42.62 ; 63.99,42.62 v2(63.97,42.64) ; 63.97,42.14 64.22,42.39 64.22,42.4 64.45,42.62 ; v2(55.32,24.41) 55.97,24.41 55.97,24.44 56.27,24.74 v2(56.69,24.74) ; 64.45,42.62 64.62,42.62 ; v2(70.62,53.95) 70.61,53.96 70.61,54.05 ; v2(64.62,42.64) 64.62,42.62
  BOTTOM w0.4: UNK4C34.1 UNK4C17.1 ; C224.2 93.46,58.8 93.45,58.79 ; C102.1 63.12,51.36 v2(62.86,51.62) ; v2(58.44,25.94) 57.91,25.94 UNK3C6.2 57.5,26.34 v2(56.73,26.34) ; v2(55.42,30.61) 55.33,30.7 UNK3R20.1 ; C206.2 93.45,49.37 93.45,49.31 ; v2(58,54) v2(57.15,54) ; C78.2 v1(76.7,33.5) ; U54.2 v1(74.8,33.8) ; UNK2C12.1 70.38,47.58 UNK2C17.2 ; UNK3C30.1 64.6,24.73 v2(64.22,24.73) ; UNK2C13.2 55.69,43.99 v2(56.08,44.38) 56.41,44.7 UNK2C11.1 ; v2(58.01,54.75) v2(57.15,54.75) ; UNK3C18.1 55.97,27.11 v2(55.78,27.31) ; v2(64.21,23.14) 64.16,23.19 UNK3C12.1 ; UNK3C58.1 64.36,35.71 v2(64.36,35.71)
  BOTTOM w0.406: v2(55.73,29.03) 55.8,29.03 57.64,27.19 58.46,27.19 v2(59.54,26.11) 59.75,25.9 60.55,25.9 60.59,25.9 ; v2(65.15,21.8) v2(63.51,21.8) ; 60.73,42.63 61.35,42.63 ; 65.58,30.01 65.25,30.34 64.22,30.34 ; 65.58,30.01 66.11,29.47 66.11,28.7 66,28.59 ; 65.58,30.01 v2(65.5,30.09) ; v2(61.21,21.8) 59.71,21.8 v2(59.31,22.2) ; v2(64.36,35.71) 64.36,35.73 64.02,36.07 63.4,36.07 ; v2(63.32,42.64) 62.69,42.64 ; v2(60.06,40.69) 59.99,40.62 v2(59.99,39.07) v2(59.99,37.19) ; v2(65.48,38.08) v2(66.83,36.73) 66.88,36.68 ; 72.64,46.89 73.85,45.68 73.85,44.3 v2(75.6,42.55) ; v2(66.24,22.84) v2(66.9,23.5) v2(67.71,24.31) v2(68.68,25.28) 69.77,26.37 v2(69.77,26.39) v2(69.77,27.59) v2(69.77,28.86) v2(69.77,30.61) v2(69.77,32.51) v2(69.77,34.24) v2(69.77,35.69) v2(69.77,37.75) 69.77,37.8 v2(68.02,39.55) ; v2(57.15,54) 55.9,54 55.9,54 53.4,54 ; v2(62.86,52.99) v2(62.86,54.74) v2(62.86,56.47) ; v3(66.34,54.79) 66.34,53.66 66.7,53.3 v2(66.7,53.29) ; UNK2C11.1 56.82,45.24 v2(58.76,45.24) v2(59.41,45.24) v2(60.06,45.24) ; 66.88,29.12 v2(66.88,28.78) 66.88,29.12 ; 66.88,29.12 v2(66.88,30.51) v2(66.88,32.26) v2(66.88,34.11) v2(66.88,35.46) 66.88,36.68 ; v2(65.99,28.58) 65.95,28.58 ; 60.78,35.99 61.9,34.88 61.9,34.36 62.29,33.96 ; v2(66.24,38.36) v2(67.56,37.04) 67.59,37.01 v2(67.59,35.51) v2(67.59,34.14) v2(67.59,32.26) v2(67.59,30.53) v2(67.59,28.59) ; 62.22,38.8 63.68,37.33 64.23,37.33 ; 62.22,38.8 62.22,39.35 ; 62.22,38.8 v2(62.2,38.81) 62.2,39.36 62.22,39.35 ; v2(61.19,39.83) 61.18,38.28 v2(62.23,37.24) v2(62.79,36.68) ; UNK3C1.1 68.51,47.58 UNK2C12.1 ; 67.05,52.63 67.03,52.65 66.3,51.92 v2(66.3,51.36) ; 71.93,35.1 72.45,35.1 v3(72.6,34.95) ; 71.93,35.1 v2(71.93,34.19) v2(71.93,32.51) v2(71.93,30.61) v2(71.93,28.83) v2(71.93,26.9) 71.93,25.48 v2(71.78,25.33) v2(70.53,24.08) v2(67.74,21.29) 66.34,19.89 v2(65.99,19.89) v2(64.59,19.89) v2(62.84,19.89) v2(61.14,19.89) v2(59.33,19.89) 58.57,19.89 v2(58.24,20.22) ; 71.93,35.1 v2(71.93,35.69) v2(71.93,37.8) 71.93,39.21 69.66,41.48 v2(69.06,41.48) ; 66.88,36.68 66.86,36.68 64.74,38.8 ; 62.22,39.35 64.23,37.33 ; 62.22,39.35 62.22,41.32 62.11,41.42 ; 62.68,42.64 v2(62.01,42.64) v2(61.36,42.64) 60.75,42.64 ; v2(64.17,31.13) 64.65,31.13 65.66,32.13 v2(65.66,32.16) v2(65.66,34.06) v2(65.66,35.91) 64.23,37.33 ; 58.76,41.42 58.8,41.38 v2(58.8,39.27) v2(58.8,38.2) v2(58.8,37.06) ; 58.76,41.42 59.31,41.97 59.39,41.97 v2(59.41,41.99) v2(60.06,41.99) ; 58.76,41.42 57.9,40.56 v2(57.9,39.88) ; 58.76,41.42 58.76,41.35 ; v2(57.15,54.75) 53.45,54.75 v1(52.93,55.27) 52.12,54.46 v1(52.12,54.36) ; v2(63.97,41.99) v2(63.97,42.64) ; v2(58.27,35.99) 59.33,35.99 59.56,35.77 59.56,35.05 v2(58.47,33.96) ; UNK3R10.1 65.11,27.26 v2(65.66,27.26) ; v2(64.67,40.74) 64.92,40.74 v2(66.01,39.65) ; v2(63.28,41.32) 63.28,40.32 v2(63.7,39.88)
  BOTTOM w0.5: 93.45,58.79 v1(93.45,59.66) ; v1(93.45,59.66) v1(94.05,60.26) ; v1(93.45,59.66) v1(93.45,60.26) v1(94.05,60.26) ; v1(93.45,59.66) v1(94.05,59.66) v1(94.05,60.26) ; C306.2 23.5,36.6 v1(23.6,36.7) ; v1(93.45,26.5) v1(93.45,25.9) v1(94.05,25.9) ; v1(93.45,26.5) v1(94.05,25.9) ; v1(93.45,26.5) 93.45,27.37 C231.2 ; v1(93.45,26.5) v1(94.05,26.5) v1(94.05,25.9) ; 84.25,59.9 84,59.65 82.75,59.65 82.3,60.1 78.5,60.1 78.05,60.55 76.3,60.55 v1(76.1,60.75) ; v1(23.6,58.65) v1(23,58.65) v1(23,59.25) ; v1(23.6,58.65) v1(23.6,59.25) v1(23,59.25) ; v1(23.6,58.65) 23.5,58.55 C331.2 ; v1(23.6,58.65) v1(23,59.25) ; v1(23.6,36.7) v1(23,37.3) ; v1(23.6,36.7) v1(23,36.7) v1(23,37.3) ; v1(23.6,36.7) v1(23.6,37.3) v1(23,37.3) ; v1(93.45,48.44) v1(94.05,47.84) ; v1(93.45,48.44) v1(93.45,47.84) v1(94.05,47.84) ; v1(93.45,48.44) v1(94.05,48.44) v1(94.05,47.84) ; v1(93.45,48.44) 93.45,49.31 ; v1(23.6,47.43) v1(23,46.83) ; v1(23.6,47.43) v1(23.6,46.83) v1(23,46.83) ; v1(23.6,47.43) v1(23,47.43) v1(23,46.83) ; v1(23.6,47.43) 23.5,47.53 C348.2 ; v1(94.05,38.32) v1(94.05,37.72) v1(93.45,37.72) ; v1(94.05,38.32) v1(93.45,38.32) v1(93.45,37.72) ; v1(94.05,38.32) v1(93.45,37.72) ; C248.2 93.45,36.85 v1(93.45,37.72) ; v1(84.75,29) 84.75,26.75 83.6,25.6 80,25.6 79.2,26.4 v1(78.8,26.4) ; v1(23,24.88) v1(23.6,24.88) v1(23.6,25.48) ; v1(23,24.88) v1(23,25.48) v1(23.6,25.48) ; v1(23,24.88) v1(23.6,25.48) ; v1(23.6,25.48) 23.5,25.58 C324.2 ; 79.22,61.38 78.3,62.3 75.65,62.3 74,63.95 74,68.3 v1(72.75,69.55) 67,69.55 T308.1 64.05,67.85 v1(64,67.8) 62.8,66.6 62.25,66.6 v1(61.9,66.25) 61.25,65.6 v1(56.5,65.6) v1(54.2,65.6) v1(53.4,65.6) v1(51.8,65.6) v1(50,65.6) 46.25,65.6 45.7,65.05 37.1,65.05 35.7,63.65 35.7,61.85 34.8,61.85 34.5,62.15 34.5,63.65 36.7,65.85 45.3,65.85 45.85,66.4 v1(50,66.4) v1(51.8,66.4) v1(53.4,66.4) v1(55,66.4) v1(57.2,66.4) 60.5,66.4 61.6,67.5 61.6,68.3 62.3,69 65.2,69 66.6,70.4 73.1,70.4 v1(74.87,68.63) 74.87,64.28 76,63.15 78.65,63.15 79.35,62.45 ; U55.2 v1(50.8,33.9)
  BOTTOM w0.635: 64.25,48.45 64.22,48.48 ; 64.25,48.45 63.97,48.17 ; 64.25,48.45 65.52,48.45 65.54,48.48 ; 64.22,48.48 65.54,48.48 ; 64.22,48.48 63.43,48.48 v2(63.32,48.5) ; 65.54,48.48 66.44,49.38 ; 63.96,48.17 63.85,48.06
  BOTTOM w1.016: 63.75,48.16 63.96,48.16
  vias: v1(0.8,59.8) v1(0.8,55.8) v1(0.8,52.6) v1(0.8,49.6) v1(0.8,46) v1(0.8,42.6) v1(0.8,39.2) v1(0.8,36) v1(0.8,32.8) v1(0.8,29.6) v1(0.8,26.8) v1(0.8,24.2) v1(0.8,21.6) v1(0.8,18.4) v1(0.8,15.6) v1(0.8,12.15) v1(0.8,8) v1(0.8,5.4) v1(0.8,2.8) v1(1.2,62.4) v1(2.8,63) v1(2.8,17.9) v1(2.9,15.4) v1(3.2,49.6) v1(3.2,46) v1(3.2,42.6) v1(3.4,26.8) v1(3.6,39) v1(3.6,36) v1(3.6,32.8) v1(3.6,0.8) v1(3.8,61) v1(3.8,57.6) v1(3.8,56) v1(3.8,54) v1(3.8,52.4) v1(4.9,17.8) v1(5,63) v1(6.4,61) v1(6.4,57.6) v1(6.4,56) v1(6.4,54) v1(7.4,63.8) v1(7.4,17.8) v1(7.8,60) v1(7.9,55.3) v1(8.1,15.2) v1(8.6,0.8) v1(8.8,61) v1(9.2,65.2) v1(9.4,15.6) v1(9.6,43.6) v1(9.6,42) v1(9.6,40.6) v1(9.6,39.2) v1(10.2,20) v1(10.4,67) v1(10.4,63.8) v1(10.4,61) v1(10.4,42) v1(10.4,39.2) v1(11,73.6) v1(11,71.4) v1(11,69) v1(11,16.8) v1(11,16.2) v1(11,15.6) v1(11,15) v1(11,14.4) v1(11.2,42.05) v1(11.8,20) v1(12,74.2) v1(13.15,42.05) v1(13.6,0.8) v1(14.8,74.15) v1(15.65,42.05) v1(15.95,31.1) v1(16,20) v1(16,0.8) v1(16.5,16.5) v1(16.5,15.8) v1(16.5,15.2) v1(16.5,14.6) v1(16.5,14) v1(16.5,13.3) v1(16.9,7.8) v1(16.9,7.1) v1(16.9,6.3) v1(16.9,5.6) v1(17.6,20.2) v1(18.2,74.2) v1(18.2,42.05) v1(18.6,0.8) v1(20,20.2) v1(20.1,42.05) v1(20.2,0.8) v1(21.2,74.2) v1(21.5,0.8) v1(21.6,63.6) v1(21.6,62.75) v1(21.6,43.3) v1(21.6,42.7) v1(21.6,42.1) v1(21.6,41.45) v1(21.6,40.8) v1(21.6,21.6) v1(22.2,63.6) v1(22.2,62.75) v1(22.2,43.3) v1(22.2,42.7) v1(22.2,42.1) v1(22.2,41.45) v1(22.2,40.8) v1(22.2,21.6) v1(22.6,0.8) v1(23,63.6) v1(23,62.75) v1(23,43.3) v1(23,42.7) v1(23,42.1) v1(23,41.45) v1(23,40.8) v1(23.6,72.2) v1(23.6,70.2) v1(23.6,68.2) v1(23.6,65.2) v1(23.6,63.6) v1(23.6,62.75) v1(23.6,0.8) v1(23.8,43.3) v1(23.8,42.7) v1(23.8,42.1) v1(23.8,41.45) v1(23.8,40.8) v1(24.6,74.2) v1(24.57,54.49) v1(24.57,53.74) v1(24.57,53.04) v1(24.57,52.34) v1(24.57,32.54) v1(24.57,31.79) v1(24.57,31.09) v1(24.57,30.39) v1(25,72.2) v1(25,70.2) v1(25,68.2) v1(25,66.8) v1(25.62,54.49) v1(25.62,53.74) v1(25.62,53.04) v1(25.62,52.34) v1(25.62,51.59) v1(25.62,32.54) v1(25.62,31.79) v1(25.62,31.09) v1(25.62,30.39) v1(25.62,29.64) v1(25.8,0.8) v1(26.4,72.2) v1(26.4,70.2) v1(26.4,68.2) v1(26.62,54.49) v1(26.62,53.74) v1(26.62,52.34) v1(26.62,51.59) v1(26.62,32.54) v1(26.62,31.79) v1(26.62,30.39) v1(26.62,29.64) v1(27.4,44) v1(27.4,41.8) v1(27.4,23) v1(27.4,21.4) v1(27.62,54.49) v1(27.62,53.74) v1(27.62,52.34) v1(27.62,51.59) v1(27.62,32.54) v1(27.62,31.79) v1(27.62,30.39) v1(27.62,29.64) v1(27.8,74.2) v1(28.4,72.2) v1(28.4,70.2) v1(28.4,68.2) v1(28.6,0.8) v1(28.67,54.49) v1(28.67,53.74) v1(28.67,52.34) v1(28.67,51.59) v1(28.67,32.54) v1(28.67,31.79) v1(28.67,30.39) v1(28.67,29.64) v1(29.65,63.05) v1(29.8,46.8) v1(29.9,23.6) v1(30,42.6) v1(30,41) v1(30.6,21.4) v1(30.8,72.2) v1(30.8,70.2) v1(30.8,68.2) v1(30.8,0.8) v1(31,74.2) v1(32,46.8) v1(32,43.4) v1(32,21.4) v1(32.4,35.6) v1(32.4,13.6) v1(32.4,12.6) v1(32.4,11.8) v1(33.2,72.2) v1(33.2,70.2) v1(33.2,68.2) v1(33.4,23.6) v1(33.4,22.2) v1(33.6,0.8) v1(34,74.2) v1(34,13.6) v1(34,12.8) v1(34.2,4.4) v1(35,13.6) v1(35,12.8) v1(35.2,15) v1(35.6,21) v1(35.6,7.6) v1(35.8,24.2) v1(35.8,11.8) v1(35.8,10.9) v1(36,16.2) v1(36,15) v1(36,13.6) v1(36,12.8) v1(36.2,4.4) v1(36.4,74.2) v1(36.4,0.8) v1(37.55,59.1) v1(37.9,52.55) v1(38,24) v1(38,22.05) v1(38.2,48.2) v1(38.2,14.7) v1(38.2,13.4) v1(38.4,45.1) v1(38.4,43.5) v1(38.6,0.8) v1(39.2,74.2) v1(39.4,48.2) v1(40.5,45.1) v1(40.7,62.35) v1(40.8,59.8) v1(41.4,34.4) v1(41.6,47.6) v1(41.6,27.4) v1(42.01,37.6) v1(41.95,5.7) v1(42.4,13.4) v1(42.4,12.6) v1(42.6,5.8) v1(42.7,47.55) v1(42.8,74.2) v1(42.8,72.2) v1(42.8,70.6) v1(42.85,22.05) v1(42.9,14.55) v1(43,59.8) v1(43,41.1) v1(43.01,36) v1(43.2,13.4) v1(43.2,12.6) v1(43.4,4.8) v1(43.6,27.4) v1(43.6,0.8) v1(43.8,35.2) v1(43.8,14.6) v1(43.8,13.85) v1(44.8,7.4) v1(45,14.2) v1(45.2,36.3) v1(45.4,6.4) v1(45.4,4.8) v1(45.45,23.4) v1(45.45,22.45) v1(45.45,21.55) v1(45.8,59.8) v1(45.8,13.4) v1(46.2,74.2) v1(47,14) v1(47.2,6.4) v1(47.2,4.8) v1(48.35,22.15) v1(48.4,5.4) v1(48.6,14.2) v1(48.6,13) v1(48.6,0.8) v1(49,74.2) v1(49.4,4.8) v1(50.65,22.15) v1(50.7,24.25) v1(50.7,23.2) v1(50.8,4.25) v1(50.9,10.75) v1(52.8,74.2) v1(52.8,72.6) v1(52.8,70.8) v1(52.8,69) v1(53,14.8) v1(53,13.6) v1(53.1,23.2) v1(53.2,26.4) v1(53.2,4.25) v1(53.4,27.2) v1(53.4,22.15) v1(53.4,12.8) v1(53.8,7.6) v1(54.4,0.8) v1(54.9,64.3) v1(55,4.25) v1(56.6,74.2) v1(56.6,12.8) v1(57,15) v1(57,14) v1(57,4.25) v1(57.2,64.3) v1(57.4,0.8) v1(57.6,18.2) v1(57.6,16.6) v1(58.2,6) v1(58.2,5) v1(58.4,11.2) v1(58.4,9.2) v1(58.6,16.6) v1(58.6,15) v1(58.6,14) v1(59.25,62.75) v1(59.8,15.8) v1(60,74.2) v1(60.4,18.4) v1(60.6,11.4) v1(60.6,0.8) v1(61.2,3.2) v1(62.2,17.6) v1(62.2,5.6) v1(62.2,5) v1(62.2,4.4) v1(62.2,3.8) v1(62.2,3.2) v1(63,3) v1(63.2,6.2) v1(63.6,74.2) v1(64.4,8.8) v1(65.4,15) v1(66.4,71.8) v1(66.55,67.7) v1(67,11) v1(67.3,65.1) v1(70,15.4) v1(70.4,14.9) v1(71.95,14.9) v1(72.6,22) v1(72.6,18.4) v1(72.8,11) v1(73.55,10.7) v1(73.8,71.8) v1(74.1,46.75) v1(74.15,39.95) v1(74.2,10.25) v1(74.8,37.85) v1(74.8,9.85) v1(75.3,50.1) v1(75.3,9.4) v1(75.65,8.9) v1(76,8.2) v1(76.25,8.7) v1(76.45,7.55) v1(76.6,71.8) v1(76.6,69.8) v1(76.6,68.4) v1(76.6,15.8) v1(76.6,8.2) v1(77,7.8) v1(77,7.2) v1(77,6.6) v1(77,6) v1(77,5.4) v1(77,4.8) v1(77,4.2) v1(77,3.6) v1(77,3) v1(77,2.4) v1(77,1.8) v1(77.4,49.9) v1(77.4,1.4) v1(77.4,0.8) v1(77.6,6.6) v1(77.6,6) v1(77.6,5.4) v1(78,1.4) v1(78,0.8) v1(78.25,22.75) v1(78.25,21.9) v1(78.2,6.6) v1(78.2,6) v1(78.2,5.4) v1(78.8,68.4) v1(79.75,45.2) v1(80.2,51) v1(80.2,44.85) v1(80.4,55) v1(80.4,54) v1(80.6,56.2) v1(81.05,51) v1(81,46.9) v1(81.6,68.4) v1(82,55.2) v1(83.25,46.95) v1(83.25,44.85) v1(83.25,43.7) v1(83.25,41) v1(83.25,39.1) v1(83.8,37.85) v1(83.8,32.3) v1(83.8,29) v1(83.75,21.25) v1(84.2,68.4) v1(84.35,40.4) v1(84.35,39.1) v1(84.4,49.2) v1(84.8,26.4) v1(85.2,31.2) v1(85.15,20) v1(85.35,24.25) v1(85.4,74.2) v1(85.4,71.4) v1(85.4,69) v1(85.8,29) v1(85.8,26.4) v1(86.2,67) v1(86.2,24.25) v1(86.4,12) v1(86.8,29) v1(87.8,20.4) v1(87.9,18.35) v1(88.38,55.5) v1(88.4,54.75) v1(88.4,53.3) v1(88.38,52.6) v1(88.38,33.56) v1(88.38,32.81) v1(88.38,31.36) v1(88.38,30.66) v1(88.6,18.35) v1(89.2,63.8) v1(89.2,44.2) v1(89.2,41) v1(89.43,55.5) v1(89.43,54.75) v1(89.43,53.3) v1(89.43,52.6) v1(89.38,33.56) v1(89.38,32.81) v1(89.38,31.36) v1(89.38,30.66) v1(89.7,23.25) v1(90.25,19.6) v1(90.2,18.4) v1(90.43,55.5) v1(90.43,54.75) v1(90.43,53.3) v1(90.43,52.6) v1(90.43,33.56) v1(90.43,32.81) v1(90.43,31.36) v1(90.43,30.66) v1(90.85,0.75) v1(91.43,55.5) v1(91.43,54.75) v1(91.43,54.05) v1(91.43,53.3) v1(91.43,52.6) v1(91.43,33.56) v1(91.43,32.81) v1(91.43,32.11) v1(91.43,31.36) v1(91.43,30.66) v1(91.6,18.4) v1(91.65,19.6) v1(92,63) v1(92.48,55.51) v1(92.5,54.85) v1(92.48,54.06) v1(92.45,53.3) v1(92.48,52.61) v1(92.48,33.56) v1(92.48,32.81) v1(92.48,32.11) v1(92.48,31.36) v1(92.48,30.66) v1(92.85,19.6) v1(92.8,18.4) v1(93.2,43.8) v1(93.2,42.4) v1(93.2,0.75) v1(93.4,57.2) v1(93.8,63) v1(93.8,18.4) v1(94,43.8) v1(94,42.4) v1(94.2,57.2) v1(94.4,17.8) v1(94.8,44.6) v1(94.8,43.8) v1(94.8,42.4) v1(94.8,41.6) v1(94.8,22.4) v1(94.8,21.8) v1(94.8,21) v1(94.8,16.6) v1(94.8,15.2) v1(94.8,13.6) v1(95.4,44.6) v1(95.5,3.65) v1(95.6,63.6) v1(95.6,43.8) v1(95.6,42.4) v1(95.6,41.6) v1(95.6,22.4) v1(95.6,21.8) v1(95.6,21) v1(95.6,12.8) v1(96.3,43.1) v1(96.4,11.8) v1(96.4,10.2) v1(96.4,8.8) v1(96.5,3.65) v1(96.6,21) v1(96.8,0.75) v1(97.4,65) v1(97.6,21) v1(97.8,8.6) v1(99,67.4) v1(99.2,19.6) v1(99.2,17.2) v1(99.2,14.2) v1(99.2,11) v1(99.2,8) v1(99.4,21) v1(99.6,73.8) v1(99.6,69.8) v1(100.2,65.2) v1(100.5,43.1) v1(102.2,74.2) v1(103.6,65.2) v1(105.2,74.2) v1(106.8,65.2) v1(106.8,63.6) v1(108.4,74.2) v1(108.8,63.6) v1(108.8,58.6) v1(108.8,48.6) v1(109.8,55.4) v1(111.6,55.4) v1(112,74.2) v1(112.4,63.6) v1(112.4,58.6) v1(112.4,48.6) v1(112.4,37.6) v1(112.8,55.4) v1(112.8,54) v1(112.8,52.2) v1(113.4,26.4) v1(113.4,23.4) v1(114.4,35.6) v1(114.6,21.8) v1(114.8,74.2) v1(116.2,72.4) v1(116.2,69.8) v1(116.2,67) v1(116.2,63.6) v1(116.2,58.6) v1(116.2,53.6) v1(116.2,48.6) v1(116.2,43.6) v1(116.2,38.6) v1(116.2,33.6) v1(116.2,28.6) v1(116.2,23.6) v2(49.9,52.8) v2(53,61.6) v2(54.13,30.23) v2(54.1,28.6) v2(54.18,26.14) v2(56.28,35.92) v2(57.2,63.6) v2(64.15,57.25) v2(65.91,45.24) v2(66.2,60) v2(70.1,42.25) v2(75.4,32.75) v2(76.6,37.9) v2(77.15,42.45) v2(77.15,41) v2(78.65,44.15) v3(53.24,34.25) v3(53.21,31.66) v3(53.16,28.4)
